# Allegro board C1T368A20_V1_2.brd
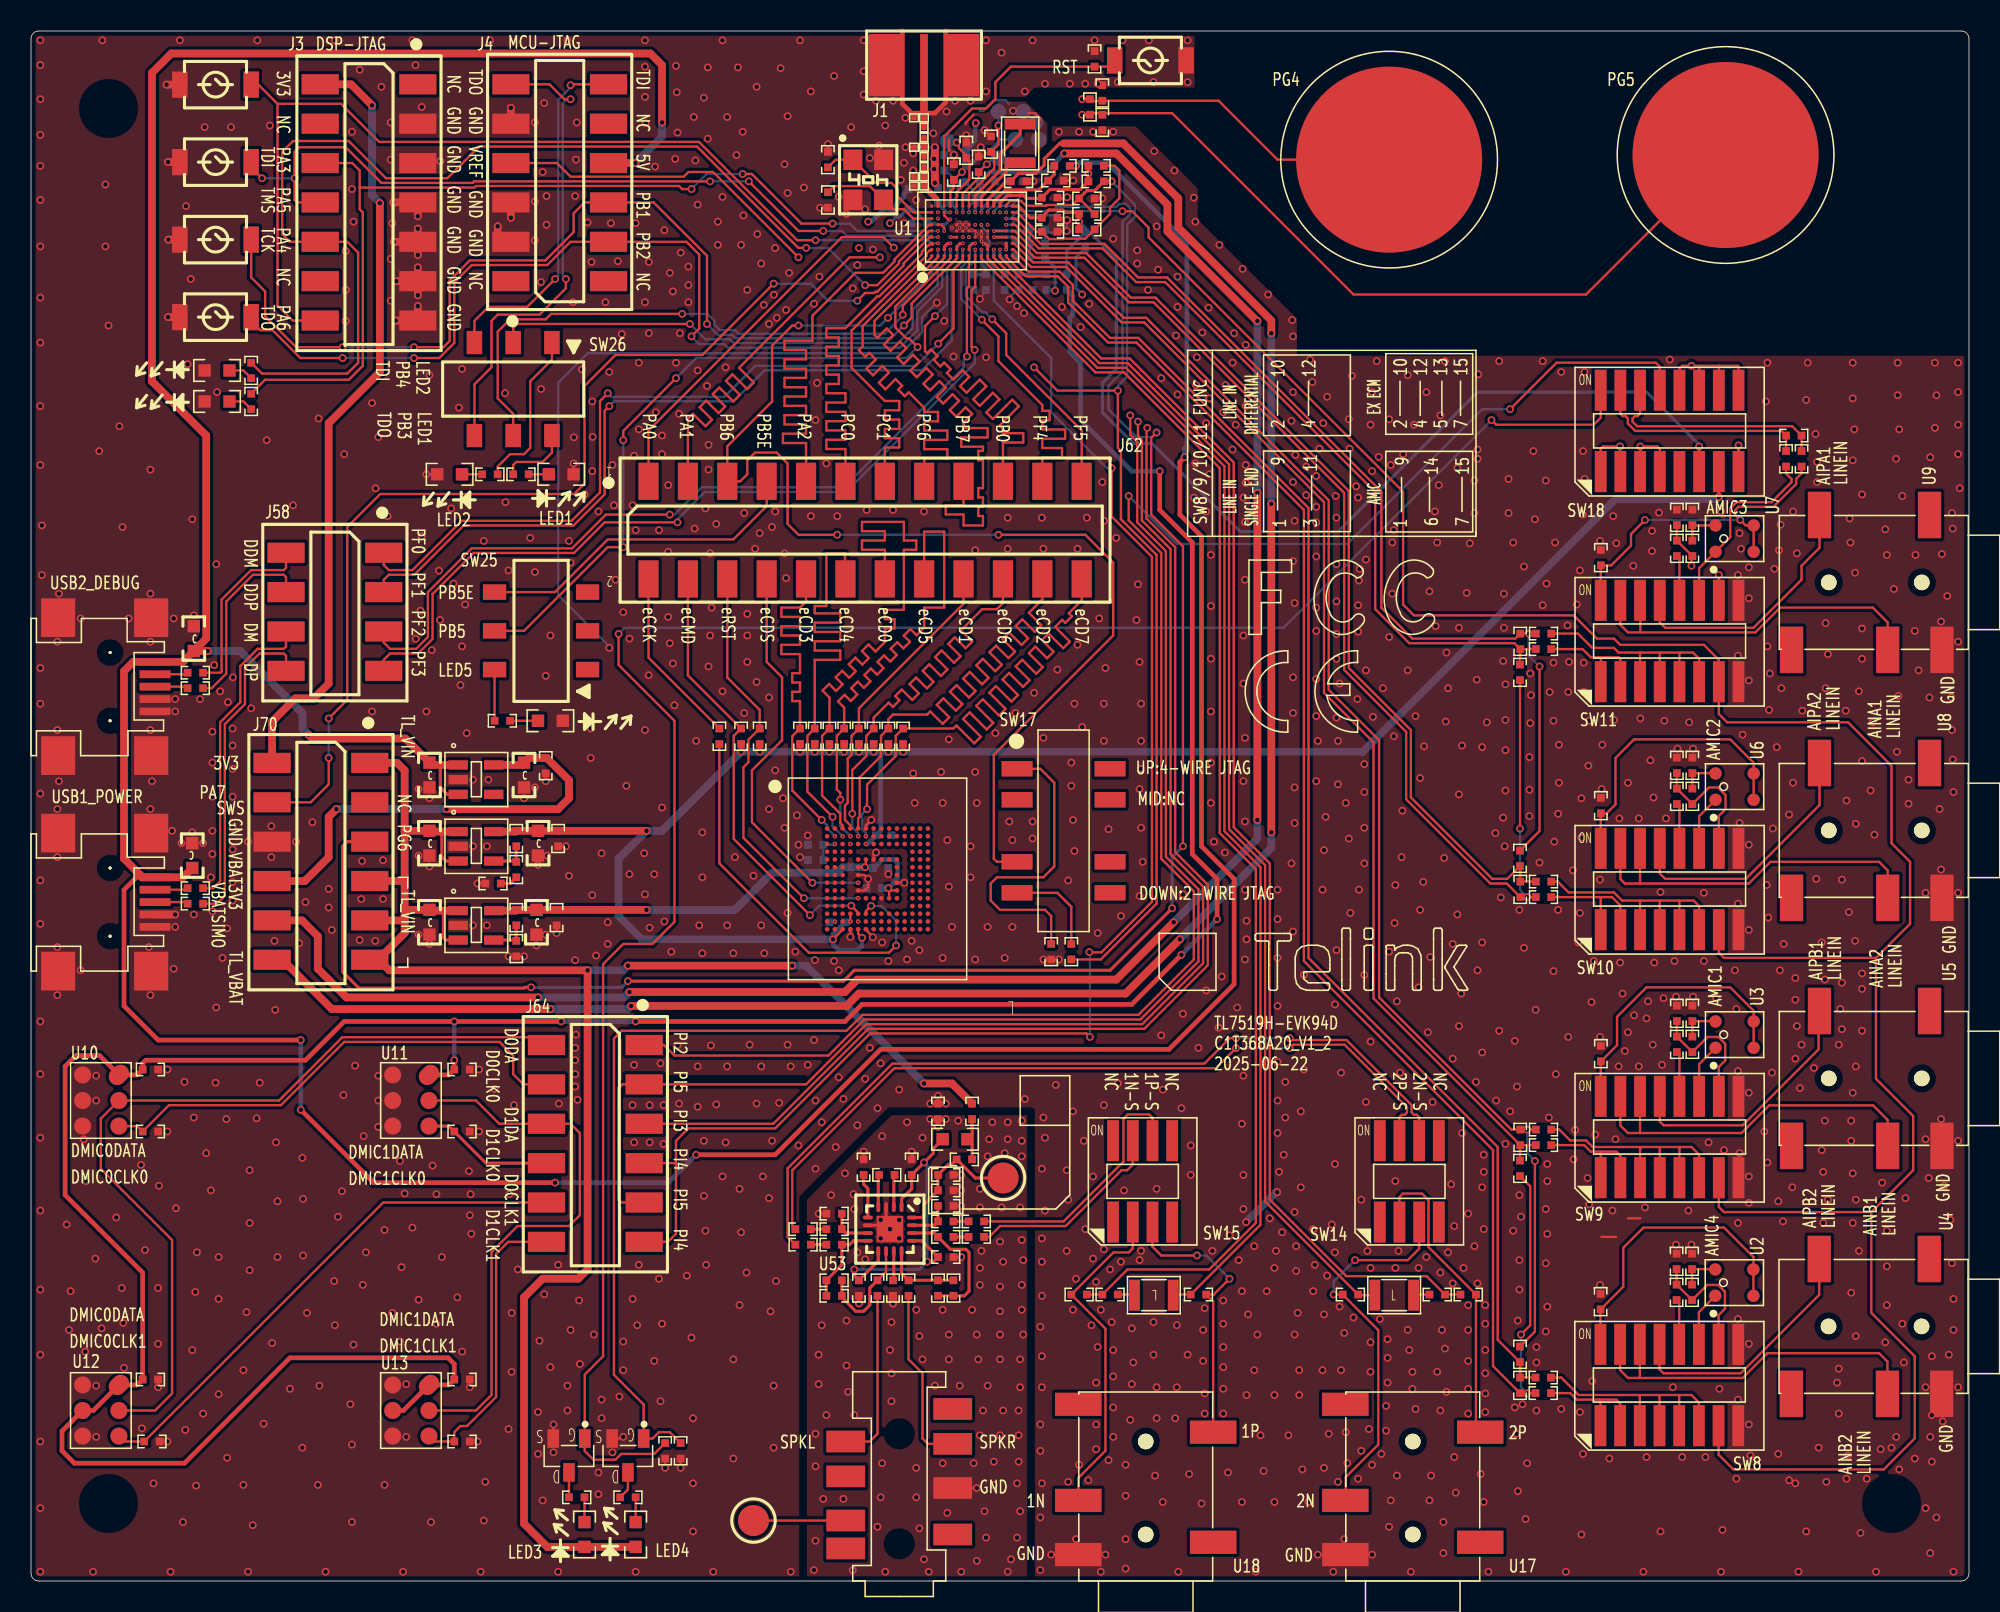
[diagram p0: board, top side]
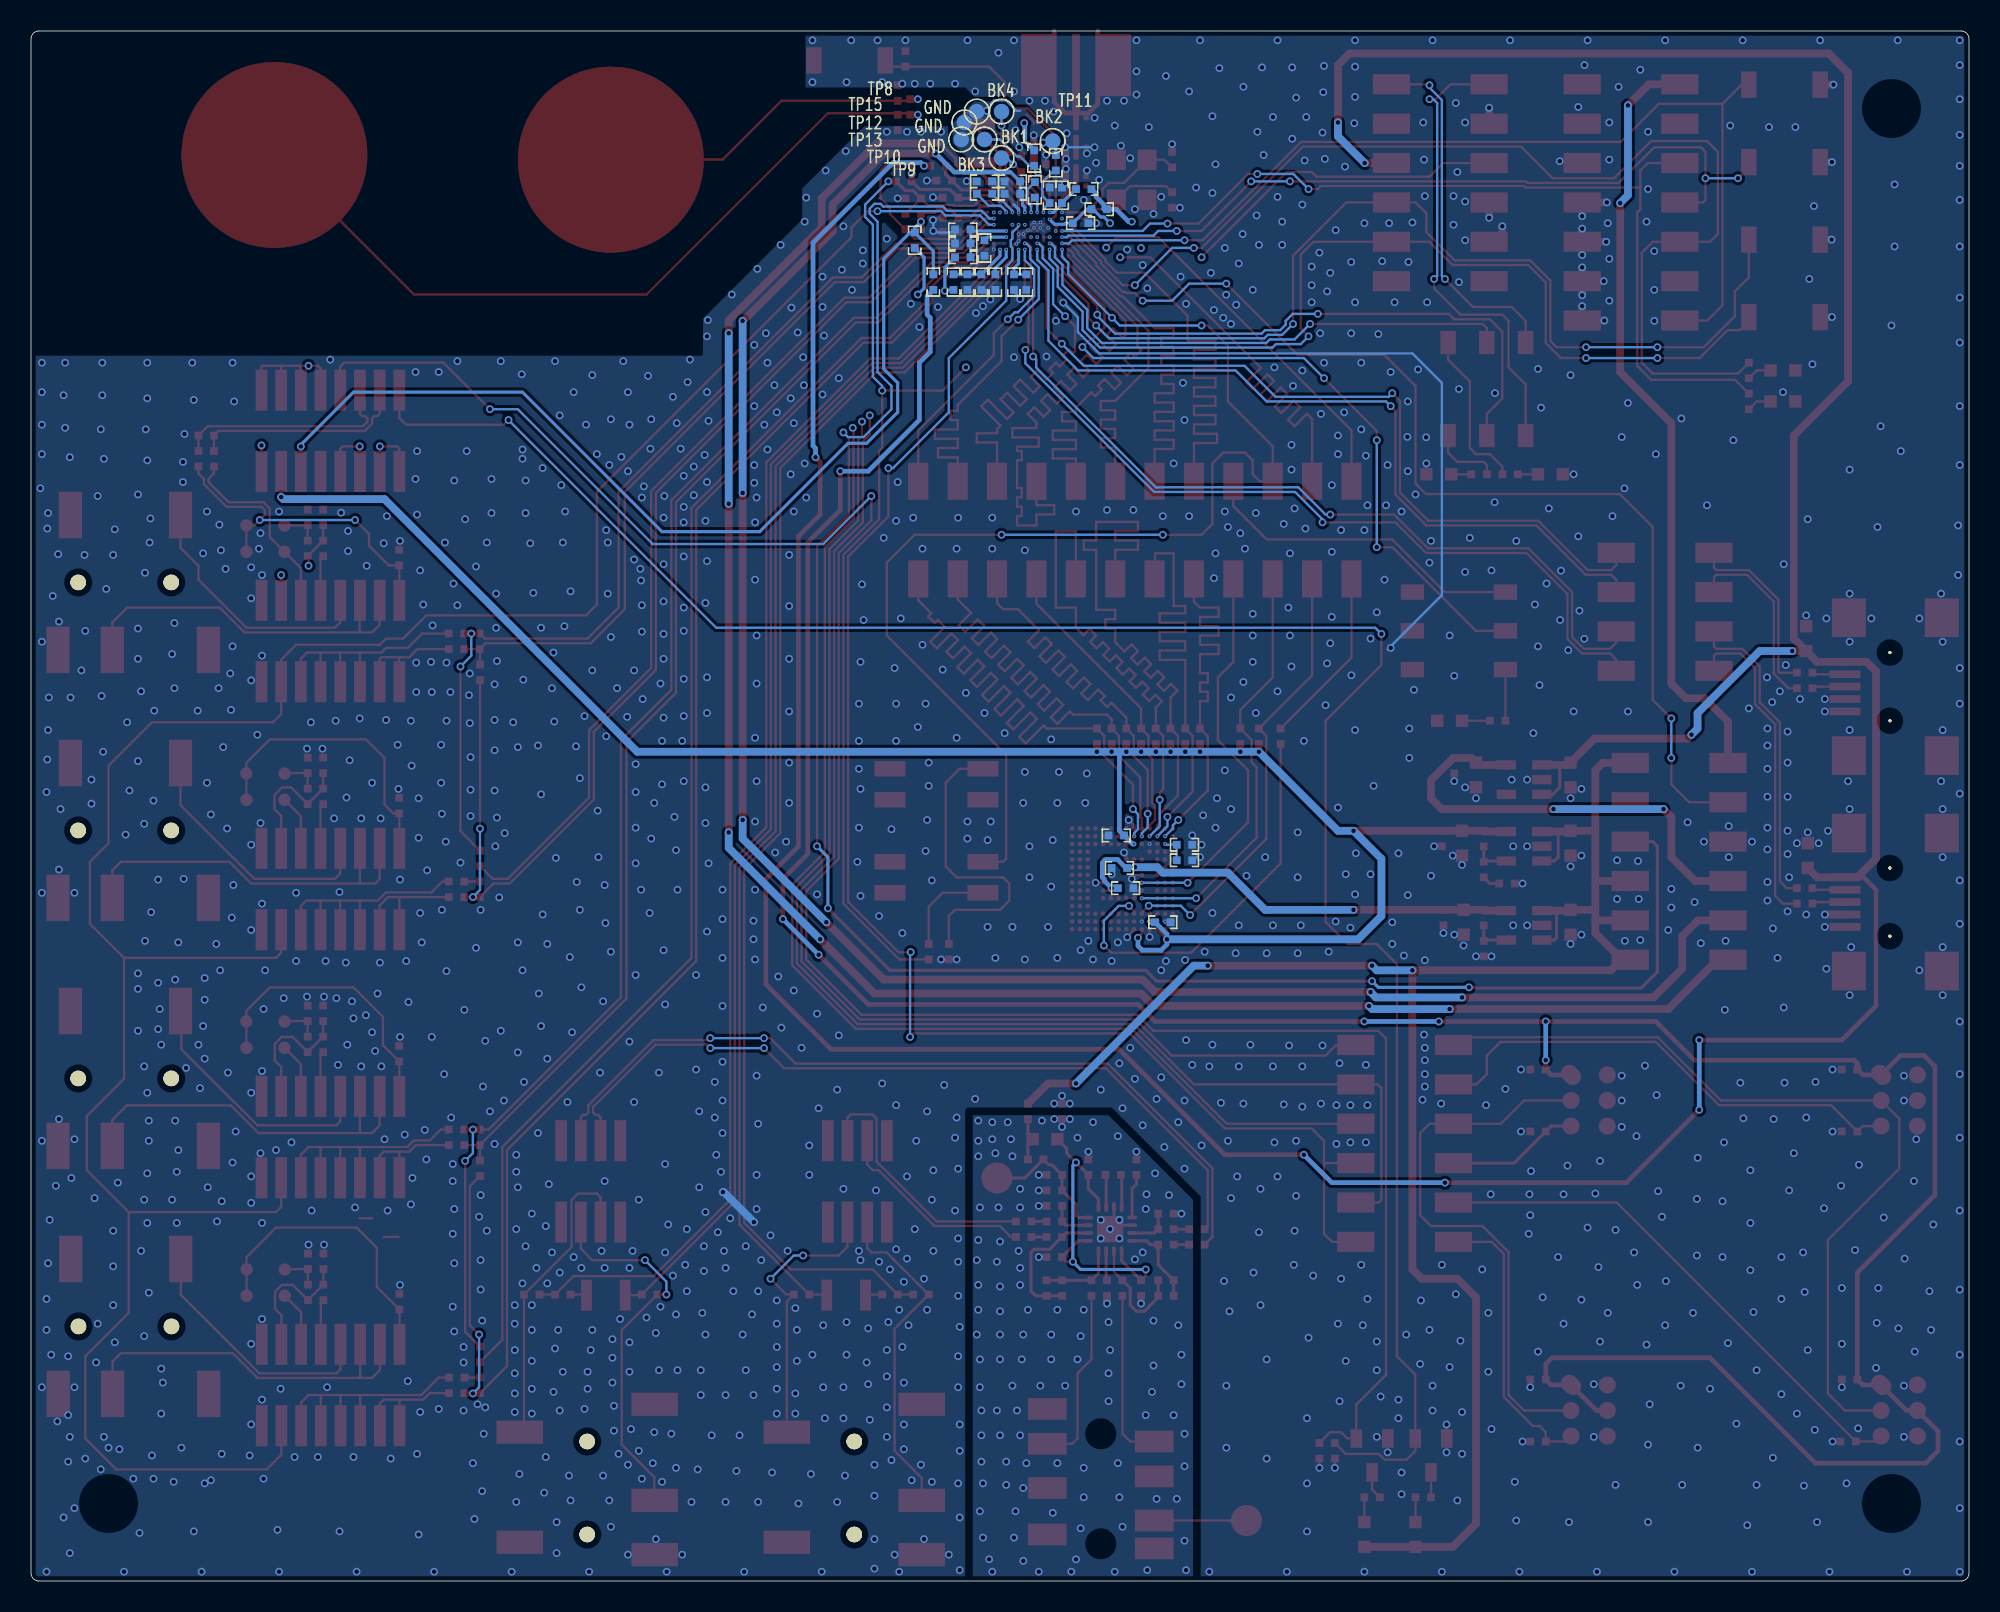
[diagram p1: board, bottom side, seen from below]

Outline 125 x 100 mm; copper layers: TOP, GND, POWER, BOTTOM. Coordinates in mm from the lower left corner of the outline.
Outline path: 0,99.5 arc(0.15,99.85) 0.5,100 124.5,100 arc(124.85,99.85) 125,99.5 125,0.5 arc(124.85,0.15) 124.5,0 0.5,0 arc(0.15,0.15) 0,0.5 0,99.5

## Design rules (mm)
constraint set DEFAULT: min track width 0.15
net group TL_EMMCCMD: nets TL_EMMCCMD TL_PA1
net group TL_EMMCD0: nets TL_EMMCD0 TL_PC1
net group TL_EMMCD1: nets TL_EMMCD1 TL_PB7
net group TL_EMMCD2: nets TL_EMMCD2 TL_PF4
net group TL_EMMCD3: nets TL_EMMCD3 TL_PA2
net group TL_EMMCD4: nets TL_EMMCD4 TL_PC0
net group TL_EMMCD5: nets TL_EMMCD5 TL_PC6
net group TL_EMMCD6: nets TL_EMMCD6 TL_PB0
net group TL_EMMCD7: nets TL_EMMCD7 TL_PF5
net group TL_EMMCDS: nets TL_EMMCDS TL_PB5_EMMC
net group TL_EMMCRSTN: nets TL_EMMCRSTN TL_PB6
net group TL_EMMCCK: nets N20915988 TL_EMMCCK TL_PA0

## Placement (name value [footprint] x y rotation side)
C2  1.8pF  [0201]  57.27 92.5 0 top
C3  NC  [0201]  57.27 94.4 0 top
C4  1uF  [0402]  68.1 89.2 0 top
C5  1uF  [0402]  59.3 89.4 90 bottom
C6  1uF  [0402]  58.5 89.4 90 bottom
C8  1uF  [0402]  68.6 98.2 90 top
C10  1uF  [0402]  57.3 87.6 180 bottom
C11  10uF  [0402]  66.1 90.35 0 top
C12  10uF  [0402]  63.7 90.31 0 top
C13  4.7uF  [0402]  62.8 83.8 270 bottom
C15  10uF  [0603C]  25.7 42.5 270 top
C16  10uF  [0402]  60.8 83.8 270 bottom
C17  0.1uF  [0402]  61.6 83.8 270 bottom
C19  10uF  [0603C]  25.7 47.6 270 top
C20  10uF  [0402]  65.7 89.25 0 top
C21  0.1uF  [0402]  34 47.9 270 top
C23  10uF  [0402]  65.7 87.95 0 top
C24  4.7uF  [0402]  63.5 86 270 bottom
C25  10uF  [0402]  64.6 83.8 270 bottom
C26  0.1uF  [0402]  63.7 83.8 270 bottom
C27  1uF  [0402]  65.7 87.05 0 top
C28  10uF  [0402]  61.7 90.3 0 bottom
C29  4.7uF  [0402]  61.92 92.7 90 top
C30  4.7uF  [0402]  61.12 91.4 90 top
C31  4.7uF  [0402]  60.33 92.3 90 top
C32  4.7uF  [0402]  59.52 90.9 90 top
C33  10uF  [0402]  64.9 86.3 0 bottom
C34  0.1uF  [0402]  64.9 87.2 0 bottom
C35  NC  [0402]  51.4 89.1 90 top
C36  NC  [0402]  51.4 91.7 270 top
C39  1uF  [0402]  107.14 20.62 90 top
C40  1uF  [0402]  107.16 36.62 90 top
C41  1uF  [0402]  106.14 20.62 90 top
C42  1uF  [0402]  106.16 36.62 90 top
C43  270nF  [0402]  97.54 13.12 0 top
C44  270nF  [0402]  97.56 29.12 0 top
C45  270nF  [0402]  97.54 12.12 0 top
C46  270nF  [0402]  97.56 28.12 0 top
C47  1uF  [0402]  107.16 68.62 90 top
C48  1uF  [0402]  107.16 52.62 90 top
C49  1uF  [0402]  106.16 52.62 90 top
C50  1uF  [0402]  106.16 68.62 90 top
C51  270nF  [0402]  97.56 61.12 0 top
C52  270nF  [0402]  97.56 45.12 0 top
C53  270nF  [0402]  97.56 60.12 0 top
C54  270nF  [0402]  97.56 44.12 0 top
C59  0.1uF  [0402]  7.7 33 0 top
C60  0.1uF  [0402]  27.8 13 0 top
C61  0.1uF  [0402]  7.7 13 0 top
C62  0.1uF  [0402]  27.8 33 0 top
C69  1uF  [0402]  53.7 26.7 90 top
C70  1uF  [0402]  55.2 26.2 180 top
C71  0.1uF  [0402]  55.6 18.9 270 top
C72  15pF  [0402]  58.5 18.9 90 top
C73  1uF  [0402]  59 20.9 0 top
C78  0R  [0402]  92.7 18.48 0 top
C79  0R  [0402]  67.6 18.48 180 top
C80  0R  [0402]  85.1 18.48 180 top
C81  0R  [0402]  75.3 18.48 0 top
C82  10uF  [0603C]  10.4 46.8 90 top
C91  10uF  [0603C]  25.7 52 270 top
C92  10uF  [0603C]  31.8 52 270 top
C93  0.1uF  [0402]  33.2 52.6 270 top
C112  1.5pF  [0201]  57.27 90.6 0 top
C113  0.1uF  [0402]  61.7 89.5 0 bottom
C427  2.2uF  [0402]  52 42.5 180 bottom
C428  2.2uF  [0402]  55 48.1 0 bottom
C429  4.7uF  [0402]  54.8 46 0 bottom
C430  4.7uF  [0402]  54.4 44.7 180 bottom
C431  0.1uF  [0402]  50.6 47.5 180 bottom
C432  0.1uF  [0402]  50.6 46.5 180 bottom
C433  10uF  [0603C]  10.5 60.8 270 top
C460  1uF  [0402]  53.4 18.9 270 top
C461  1uF  [0402]  56.8 26.7 90 top
C462  4.7uF  [0402]  60.97 22.2 180 top
C463  4.7uF  [0402]  60.97 23.2 180 top
C464  4.7uF  [0402]  49.8 22.7 0 top
C465  4.7uF  [0402]  49.8 21.7 0 top
C466  0.1uF  [0402]  59 26.2 0 top
C467  15pF  [0402]  51.8 18.4 0 top
C468  10uF  [0603C]  32.6 42.5 270 top
C469  0.1uF  [0402]  33.9 42.8 270 top
C470  10uF  [0603C]  32.7 47.6 270 top
C471  510pF  [0402]  63.5 89.5 180 bottom
C472  510pF  [0402]  60.25 89.75 270 bottom
C473  NC  [0402]  68.3 95.1 270 top
C474  5.1pF  [0402]  69.1 94.1 270 top
C475  5.1pF  [0402]  69.1 96 270 top
C476  270nF  [0402]  113.2 72.4 270 top
C477  270nF  [0402]  114.2 72.4 270 top
D1  Blue  [0603-LED]  35.7 3 90 top
D5  ULC0322P10LV  [0201]  57.27 90 180 top
D6  Yellow  [0603-LED]  33.5 55.5 0 top
D8  Red  [0603-LED]  27 71.4 180 top
D9  White  [0603-LED]  34.2 71.4 0 top
D10  Green  [0603-LED]  39 3 90 top
D11  Green  [0603-LED]  12 78.1 180 top
D12  Blue  [0603-LED]  12 76.1 180 top
J1  RFIN  [SMA-H]  57.6 97.8 270 top
J3  DSP_JTAG  [SMD254M-2X7_RX1_30Y2_40]  21.8 88.94 90 top
J4  D25_JTAG  [SMD254M-2X6_RX1_30Y2_40]  34.1 90.21 270 top
J21  USB_MiniABF  [USB-MINI-F5]  8 43.8 270 top
J22  USB_MiniABF  [USB-MINI-F5]  8 57.7 270 top
J57  M+L/R  [PJ-382-8P]  56 -1 90 top
J58  USB  [SMD254M-2X4_RX1_30Y2_40]  19.6 62.53 90 top
J62  EMMC  [SMD254M-2X12_RX1_30Y2_40]  53.8 67.8 180 top
J64  DMIC2  [SMD254M-2X6_RX1_30Y2_40]  36.4 28.23 90 top
J70  SWSPWR  [SMD254M-2X6_RX1_30Y2_40]  18.7 46.43 90 top
L1  3nH  [0201]  57.6 91.55 90 top
L2  1.5nH  [0201]  57.6 93.45 90 top
L3  EFE201612E-1R0M  [1008L]  63.8 92.75 270 top
L5  NC  [1008L]  87.92 18.44 0 top
L6  NC  [1008L]  72.42 18.44 180 top
L11  BEAD-600R  [0603L]  59.6 28.5 180 top
Q2  SI2302  [MOS_SOT-23]  34.7 8.1 180 top
Q3  SI2302  [MOS_SOT-23]  38.5 8.1 180 top
R5  1K  [0402]  35.2 5.4 180 top
R8  2.2K  [0402]  107.16 34.62 90 top
R9  2.2K  [0402]  106.14 18.62 90 top
R10  2.2K  [0402]  107.14 18.62 90 top
R11  2.2K  [0402]  106.16 34.62 90 top
R12  0R  [0402]  101.26 34.02 90 top
R13  0R  [0402]  101.24 18.02 90 top
R14  NC  [0402]  96.04 12.62 270 top
R15  NC  [0402]  96.06 28.62 270 top
R16  2.2K  [0402]  107.16 50.62 90 top
R17  2.2K  [0402]  106.16 66.62 90 top
R18  2.2K  [0402]  106.16 50.62 90 top
R19  2.2K  [0402]  107.16 66.62 90 top
R20  0R  [0402]  101.26 50.02 90 top
R21  0R  [0402]  101.26 66.02 90 top
R22  NC  [0402]  96.06 44.62 270 top
R23  NC  [0402]  96.06 60.62 270 top
R24  100K  [0402]  7.7 29 180 top
R25  100K  [0402]  27.8 29 180 top
R26  100K  [0402]  7.8 9 180 top
R27  100K  [0402]  27.8 9 180 top
R30  20K / 1%  [0402]  59 23.2 180 top
R31  20K / 1%  [0402]  59 24.2 180 top
R35  1K  [0402]  65.8 40.6 90 top
R36  1K  [0402]  67.1 40.6 90 top
R38  0R  [0402]  56.6 18.9 270 top
R39  20K / 1%  [0402]  59.5 18.9 90 top
R43  NC  [0402]  90.7 18.48 180 top
R44  NC  [0402]  69.6 18.48 0 top
R45  NC/2R  [0402]  66.5 91.3 180 top
R47  33  [0402R]  10.6 44.7 0 top
R48  33  [0402R]  10.6 43.7 0 top
R50  100K  [0402]  60.2 27.2 180 top
R53  33  [0402R]  10.6 58.6 0 top
R55  33  [0402R]  10.6 57.6 0 top
R73  NC  [0402]  96.04 14.62 90 top
R74  NC  [0402]  96.04 26.62 90 top
R75  NC  [0402]  96.04 46.62 90 top
R76  NC  [0402]  96.04 58.62 90 top
R78  0R  [0402]  63.5 90.3 0 bottom
R599  10K  [0402]  45.8 54.5 90 top
R601  10K  [0402]  51.5 54.5 90 top
R602  10K  [0402]  53.4 54.5 90 top
R603  10K  [0402]  55.3 54.5 90 top
R604  10K  [0402]  49.6 54.5 90 top
R605  10K  [0402]  50.55 54.5 90 top
R606  10K  [0402]  52.45 54.5 90 top
R607  10K  [0402]  54.35 54.5 90 top
R608  10K  [0402]  56.25 54.5 90 top
R661  10K  [0402]  47 54.5 90 top
R666  27R  [0402]  44.4 54.5 270 top
R668  20K / 1%  [0402]  59 22.2 180 top
R687  20K / 1%  [0402]  51.8 23.7 0 top
R688  20K / 1%  [0402]  51.8 22.7 0 top
R689  20K / 1%  [0402]  51.8 21.7 0 top
R690  0R  [0402]  54.6 18.9 270 top
R692  20K / 1%  [0402]  51.8 19.4 0 top
R711  0R  [0402]  58.5 30.3 270 top
R712  1M  [0402]  59 25.2 0 top
R713  0R  [0402]  60.7 30.3 270 top
R715  45.3K-1%  [0402]  31.3 42.8 270 top
R717  10K-1%  [0402]  31.3 40.8 270 top
R718  NC  [0402]  113.7 73.9 0 top
R721  45.3K-1%  [0402]  31.3 47.9 270 top
R723  12.4K-1%  [0402]  31.3 45.9 270 top
R724  9.1K-1%  [0402]  29.8 45 180 top
R725  1K  [0402]  30.4 55.5 0 top
R727  1K  [0402]  29.6 71.4 180 top
R728  1K  [0402]  31.6 71.4 0 top
R729  1K  [0402]  38.5 5.4 180 top
R730  0R/NC  [0402]  68.7 90.3 0 top
R731  NC/0R  [0402]  68.1 88.2 0 top
R732  0R/NC  [0402]  68.7 91.3 0 top
R733  NC/0R  [0402]  68.1 87.2 0 top
R734  0R/NC  [0402]  66.8 83.8 270 bottom
R735  0R/NC  [0402]  58.9 91.5 270 bottom
R736  NC/0R  [0402]  56.1 88.5 180 bottom
R737  0R/NC  [0402]  57.1 89.8 180 bottom
R738  0R/NC  [0402]  64.9 85.4 0 bottom
R739  0R/NC  [0402]  65.5 83.8 270 bottom
R740  0R/NC  [0402]  60.3 91.8 90 bottom
R741  0R/NC  [0402]  68 86.5 270 bottom
R742  10K  [0402]  41.9 8.4 270 top
R743  10K  [0402]  40.9 8.4 270 top
R744  1K  [0402]  14.2 78.1 270 top
R745  1K  [0402]  14.2 76.1 270 top
SP5  SolderPad200  [TP200]  62.7 26 0 top
SP6  SolderPad200  [TP200]  46.6 3.9 90 top
SW1  But1  [BUTSMD2PX4_00Y3_00_NH]  72.2 98.1 90 top
SW8  DU-08P  [EHS-JH_1P27_8X2]  105.67 12.64 0 top
SW9  DU-08P  [EHS-JH_1P27_8X2]  105.69 28.64 0 top
SW10  DU-08P  [EHS-JH_1P27_8X2]  105.69 44.64 0 top
SW11  DU-08P  [EHS-JH_1P27_8X2]  105.69 60.64 0 top
SW14  DU-04P  [EHS-JH_1P27_4X2]  88.9 25.78 0 top
SW15  DU-04P  [EHS-JH_1P27_4X2]  71.7 25.78 0 top
SW17  MINI_SLIDE_SWITCH  [SW-SMD-8PIN-12P95X3P5-2]  66.6 48.4 270 top
SW18  DU-08P  [EHS-JH_1P27_8X2]  105.69 74.2 0 top
SW20  BUT  [BUTSMD2PX4_00Y3_00_NH]  11.9 86.54 270 top
SW21  BUT  [BUTSMD2PX4_00Y3_00_NH]  11.9 81.54 270 top
SW23  BUT  [BUTSMD2PX4_00Y3_00_NH]  11.9 91.54 270 top
SW24  BUT  [BUTSMD2PX4_00Y3_00_NH]  11.9 96.54 270 top
SW25  LED+EMMC  [SW-SMD-6PIN-9P1X3P5-2P5]  32.9 61.3 270 top
SW26  LED+JTAG  [SW-SMD-6PIN-9P1X3P5-2P5]  31.1 76.9 0 top
TP5  CTB PAD4  [TP12MM]  87.6 91.7 0 top
TP7  CTB PAD  [TP12MM]  109.3 92 0 top
TP8  BK4  [TP100]  62.4 94.8 180 bottom
TP9  BK3  [TP100]  62.4 91.8 180 bottom
TP10  BK1  [TP100]  63.5 93 180 bottom
TP11  BK2  [TP100]  59.1 92.9 180 bottom
TP12  GND  [TP100]  64.8 94.1 180 bottom
TP13  GND  [TP100]  65 93 180 bottom
TP15  GND  [TP100]  64 94.8 180 bottom
U1  TL7519H  [BGA_4X6_94PIN_0P4]  60.7 87.1 90 top
U2  WMM7037AT2  [GA_BFA423_A83]  109.86 19.25 90 top
U3  WMM7037AT2  [GA_BFA423_A83]  109.88 35.25 90 top
U4  PJ327  [PJ-327]  124.94 16.42 270 top
U5  PJ327  [PJ-327]  124.96 32.42 270 top
U6  WMM7037AT2  [GA_BFA423_A83]  109.88 51.25 90 top
U7  WMM7037AT2  [GA_BFA423_A83]  109.88 67.25 90 top
U8  PJ327  [PJ-327]  124.96 48.42 270 top
U9  PJ327  [PJ-327]  124.96 64.42 270 top
U10  WMM7047DTFN0  [DMIC_SPM0423HM4H-WB]  4.5 31 270 top
U11  WMM7047DTFN0  [DMIC_SPM0423HM4H-WB]  24.5 31 270 top
U12  WMM7047DTFN0  [DMIC_SPM0423HM4H-WB]  4.5 11 270 top
U13  WMM7047DTFN0  [DMIC_SPM0423HM4H-WB]  24.5 11 270 top
U17  PJ327  [PJ-327]  89.12 0 180 top
U18  PJ327  [PJ-327]  71.9 0 180 top
U21  CE1132-3.3V  [SOT-23-5]  28.7 51.7 270 top
U53  MAX97220AETE+  [QFN_3X3_16PIN_0P5_1P70X1P70]  55.4 22.7 270 top
U54  CE6300-ADJ  [SOT-23-5]  28.7 42.3 270 top
U55  CE6300-ADJ  [SOT-23-5]  28.7 47.4 270 top
U56  MKEV008GCB-SC510  [FBGA153]  54.6 45.3 0 top
Y2  48MHz-6pF-+/-10ppm  [OSCCC250X320X110]  54 90.4 0 top

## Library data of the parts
C2 C3 C112 = C1608_NC: Tolerance: RichardLC; User Part Number: pn
C4-C6 C8 C10-C13 C16 C17 C20 C21 C23-C34 C39-C54 C59-C62 C69-C73 C93 C113 C427-C432 C460-C467 C469 C471-C477 = C1005X5R1C104K
C15 C19 C82 C91 C92 C433 C468 C470 = C1608X5R0J106M
C35 C36 = C1005_NC
C78-C81 = C1005X5R1C105K
D1 D6 D8-D12 = 0603D_Green
D5 = ESD5B5_0.0ST1G: Tolerance: RichardLC; User Part Number: pn
J1 = SMA_JACK_2
J3 = CON_0.54mm_2x7: Tolerance: RichardLC
J4 J64 J70 = HEADER 6X2: Tolerance: RichardLC
J21 J22 = USB_MiniABF_5pin: Tolerance: RichardLC; User Part Number: pn
J57 = PJ327_2
J58 = HEADER 4X2: Tolerance: RichardLC
J62 = HEADER 12X2: Tolerance: RichardLC; signal model: HEADER_12X2_SMD254M-2X12_RX1_30Y2_40_EMMC_EMMC
L1 L2 L5 L6 = MLK1608_000R: Tolerance: RichardLC; User Part Number: pn
L3 = IND: Tolerance: RichardLC; User Part Number: pn
L11 = IND
Q2 Q3 = NMOS_SI2302
R5 R715 R717 R721 R723-R725 R727-R729 R744 R745 = RS0402K102JT
R8-R27 R30 R31 R38 R39 R43-R45 R50 R73-R76 R668 R687-R690 R692 R711-R713 R718 R730-R741 = RS0402K104JT
R35 R36 R742 R743 = RS0402K103JT
R47 R48 R53 R55 = RS0603K330JT
R78 = RS0603K102JT
R599 R601-R608 R661 = RS0402K330JT
R666 = RS0402K330JT: signal model: RS0402K330JT_0402_27R_27R
SP5 SP6 = SolderPad200: User Part Number: pn; Tolerance: RichardLC
SW1 SW20 SW21 SW23 SW24 = SW2PIN_3x4
SW8-SW11 SW18 = EHS-JH-108: Tolerance: RichardLC
SW14 SW15 = EHS-JH-104: Tolerance: RichardLC
SW17 = MINI_SLIDE_SWITCH
SW25 SW26 = SW_SL_DPDT: User Part Number: pn; Tolerance: RichardLC
TP5 TP7 = TEST POINT
TP8-TP13 TP15 = TestPad100
U1 = TL7519H-BGA94
U2 U3 U6 U7 = MULPS4CX-RM5_0
U4 U5 U8 U9 U17 U18 = PJ327
U10-U13 = LD1117/SO_0
U21 = XC6219_5.3V_SOT-23-5
U53 = TLSR8368EP16_1
U54 U55 = XC6219_1.3V_SOT-23-5
U56 = H26M88002AMR
Y2 = CRYSTAL4/SM_0

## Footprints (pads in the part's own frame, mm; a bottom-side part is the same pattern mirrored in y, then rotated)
0201
  rect 0.35x0.33 smd: 1(-0.325,0) 2(0.325,0)
0402
  rect 0.5x0.5 smd: 1(-0.5,0) 2(0.5,0)
0402R
  rect 0.5x0.5 smd: 1(-0.5,0) 2(0.5,0)
0603-LED
  rect 0.8x0.8 smd: A(-0.8,0) C(0.8,0)
0603C
  rect 0.8x0.8 smd: 1(-0.8,0) 2(0.8,0)
0603L
  rect 0.8x0.8 smd: 1(-0.8,0) 2(0.8,0)
1008L
  rect 0.7x2 smd: 1(-1.25,0) 2(1.25,0)
BGA_4X6_94PIN_0P4
  round 0.22 smd: A1(-1.6,2.6) A2(-1.2,2.6) A3(-0.8,2.6) A4(-0.4,2.6) A5(0,2.6) A6(0.4,2.6) A7(0.8,2.6) A8(1.2,2.6) A9(1.6,2.6) B1(-1.6,2.2) B2(-1.2,2.2) B3(-0.8,2.2) B4(-0.4,2.2) B5(0,2.2) B6(0.4,2.2) B7(0.8,2.2) B8(1.2,2.2) B9(1.6,2.2) C1(-1.6,1.8) C2(-1.2,1.8) C8(1.2,1.8) C9(1.6,1.8) D1(-1.6,1.4) D2(-1.2,1.4) D8(1.2,1.4) D9(1.6,1.4) E1(-1.6,1) E2(-1.2,1) E4(-0.4,1) E5(0,1) E6(0.4,1) E8(1.2,1) E9(1.6,1) F1(-1.6,0.6) F2(-1.2,0.6) F4(-0.4,0.6) F5(0,0.6) F6(0.4,0.6) F8(1.2,0.6) F9(1.6,0.6) G1(-1.6,0.2) G2(-1.2,0.2) G4(-0.4,0.2) G5(0,0.2) G6(0.4,0.2) G8(1.2,0.2) G9(1.6,0.2) H1(-1.6,-0.2) H2(-1.2,-0.2) H4(-0.4,-0.2) H5(0,-0.2) H6(0.4,-0.2) H8(1.2,-0.2) H9(1.6,-0.2) J1(-1.6,-0.6) J2(-1.2,-0.6) J4(-0.4,-0.6) J5(0,-0.6) J6(0.4,-0.6) J8(1.2,-0.6) J9(1.6,-0.6) K1(-1.6,-1) K2(-1.2,-1) K4(-0.4,-1) K5(0,-1) K6(0.4,-1) K8(1.2,-1) K9(1.6,-1) L1(-1.6,-1.4) L2(-1.2,-1.4) L8(1.2,-1.4) L9(1.6,-1.4) M1(-1.6,-1.8) M2(-1.2,-1.8) M8(1.2,-1.8) M9(1.6,-1.8) N1(-1.6,-2.2) N2(-1.2,-2.2) N3(-0.8,-2.2) N4(-0.4,-2.2) N5(0,-2.2) N6(0.4,-2.2) N7(0.8,-2.2) N8(1.2,-2.2) N9(1.6,-2.2) P1(-1.6,-2.6) P2(-1.2,-2.6) P3(-0.8,-2.6) P4(-0.4,-2.6) P5(0,-2.6) P6(0.4,-2.6) P7(0.8,-2.6) P8(1.2,-2.6) P9(1.6,-2.6)
BUTSMD2PX4_00Y3_00_NH
  rect 1.7x1 smd: 1(0,2.3) 2(0,-2.3)
DMIC_SPM0423HM4H-WB
  round 1.1 smd: 1(-1.65,-1.17) 2(0,-1.17) 3(1.65,-1.17) 4(1.65,1.17) 5(0,1.17)
  oval 1.4x1.1 smd rot 135: 6(-1.65,1.17)
EHS-JH_1P27_4X2
  rect 0.76x2.65 smd: 1(-1.905,-2.625) 2(-0.635,-2.625) 3(0.635,-2.625) 4(1.905,-2.625) 5(-1.905,2.625) 6(-0.635,2.625) 7(0.635,2.625) 8(1.905,2.625)
EHS-JH_1P27_8X2
  rect 0.76x2.65 smd: 1(-4.445,-2.625) 2(-3.175,-2.625) 3(-1.905,-2.625) 4(-0.635,-2.625) 5(0.635,-2.625) 6(1.905,-2.625) 7(3.175,-2.625) 8(4.445,-2.625) 9(-4.445,2.625) 10(-3.175,2.625) 11(-1.905,2.625) 12(-0.635,2.625) 13(0.635,2.625) 14(1.905,2.625) 15(3.175,2.625) 16(4.445,2.625)
FBGA153
  round 0.3 smd: A1(-3.25,3.25) A2(-2.75,3.25) A3(-2.25,3.25) A4(-1.75,3.25) A5(-1.25,3.25) A6(-0.75,3.25) A7(-0.25,3.25) A8(0.25,3.25) A9(0.75,3.25) A10(1.25,3.25) A11(1.75,3.25) A12(2.25,3.25) A13(2.75,3.25) A14(3.25,3.25) B1(-3.25,2.75) B2(-2.75,2.75) B3(-2.25,2.75) B4(-1.75,2.75) B5(-1.25,2.75) B6(-0.75,2.75) B7(-0.25,2.75) B8(0.25,2.75) B9(0.75,2.75) B10(1.25,2.75) B11(1.75,2.75) B12(2.25,2.75) B13(2.75,2.75) B14(3.25,2.75) C1(-3.25,2.25) C2(-2.75,2.25) C3(-2.25,2.25) C4(-1.75,2.25) C5(-1.25,2.25) C6(-0.75,2.25) C7(-0.25,2.25) C8(0.25,2.25) C9(0.75,2.25) C10(1.25,2.25) C11(1.75,2.25) C12(2.25,2.25) C13(2.75,2.25) C14(3.25,2.25) D1(-3.25,1.75) D2(-2.75,1.75) D3(-2.25,1.75) D4(-1.75,1.75) D12(2.25,1.75) D13(2.75,1.75) D14(3.25,1.75) E1(-3.25,1.25) E2(-2.75,1.25) E3(-2.25,1.25) E5(-1.25,1.25) E6(-0.75,1.25) E7(-0.25,1.25) E8(0.25,1.25) E9(0.75,1.25) E10(1.25,1.25) E12(2.25,1.25) E13(2.75,1.25) E14(3.25,1.25) F1(-3.25,0.75) F2(-2.75,0.75) F3(-2.25,0.75) F5(-1.25,0.75) F10(1.25,0.75) F12(2.25,0.75) F13(2.75,0.75) F14(3.25,0.75) G1(-3.25,0.25) G2(-2.75,0.25) G3(-2.25,0.25) G5(-1.25,0.25) G10(1.25,0.25) G12(2.25,0.25) G13(2.75,0.25) G14(3.25,0.25) H1(-3.25,-0.25) H2(-2.75,-0.25) H3(-2.25,-0.25) H5(-1.25,-0.25) H10(1.25,-0.25) H12(2.25,-0.25) H13(2.75,-0.25) H14(3.25,-0.25) J1(-3.25,-0.75) J2(-2.75,-0.75) J3(-2.25,-0.75) J5(-1.25,-0.75) J10(1.25,-0.75) J12(2.25,-0.75) J13(2.75,-0.75) J14(3.25,-0.75) K1(-3.25,-1.25) K2(-2.75,-1.25) K3(-2.25,-1.25) K5(-1.25,-1.25) K6(-0.75,-1.25) K7(-0.25,-1.25) K8(0.25,-1.25) K9(0.75,-1.25) K10(1.25,-1.25) K12(2.25,-1.25) K13(2.75,-1.25) K14(3.25,-1.25) L1(-3.25,-1.75) L2(-2.75,-1.75) L3(-2.25,-1.75) L12(2.25,-1.75) L13(2.75,-1.75) L14(3.25,-1.75) M1(-3.25,-2.25) M2(-2.75,-2.25) M3(-2.25,-2.25) M4(-1.75,-2.25) M5(-1.25,-2.25) M6(-0.75,-2.25) M7(-0.25,-2.25) M8(0.25,-2.25) M9(0.75,-2.25) M10(1.25,-2.25) M11(1.75,-2.25) M12(2.25,-2.25) M13(2.75,-2.25) M14(3.25,-2.25) N1(-3.25,-2.75) N2(-2.75,-2.75) N3(-2.25,-2.75) N4(-1.75,-2.75) N5(-1.25,-2.75) N6(-0.75,-2.75) N7(-0.25,-2.75) N8(0.25,-2.75) N9(0.75,-2.75) N10(1.25,-2.75) N11(1.75,-2.75) N12(2.25,-2.75) N13(2.75,-2.75) N14(3.25,-2.75) P1(-3.25,-3.25) P2(-2.75,-3.25) P3(-2.25,-3.25) P4(-1.75,-3.25) P5(-1.25,-3.25) P6(-0.75,-3.25) P7(-0.25,-3.25) P8(0.25,-3.25) P9(0.75,-3.25) P10(1.25,-3.25) P11(1.75,-3.25) P12(2.25,-3.25) P13(2.75,-3.25) P14(3.25,-3.25)
GA_BFA423_A83
  round 0.8 smd: 1(-0.85,1.23) 2(-0.85,-1.23) 3(0.85,-1.23) 4(0.85,1.23)
MOS_SOT-23
  rect 0.75x1.2 smd: 1(-1.016,-1.092) 2(1.016,-1.092) 3(0,1.092)
OSCCC250X320X110
  rect 1.22x1.32 smd: 1(-0.991,1.29) 2(-0.991,-1.29) 3(0.991,-1.29) 4(0.991,1.29)
PJ-327
  round 1 hole 1 unplated: (0,-3) (0,-9)
  rect 3x1.5 smd: 1(-4.35,-2.5) 2(4.35,-5.2) 3(-4.35,-9.6) 4(4.35,-11.4) 5(4.35,-1.7)
PJ-382-8P
  rect 1.4x2.5 smd: 1(4,-3.45) 2(7,-3.45) 3(9.85,-3.45) 4(12.1,-3.45) 5(3.1,3.45) 6(4.9,3.45) 7(7.75,3.45) 8(10,3.45)
QFN_3X3_16PIN_0P5_1P70X1P70
  oval 0.65x0.25 smd: 1(-1.425,0.75) 2(-1.425,0.25) 3(-1.425,-0.25) 4(-1.425,-0.75) 9(1.425,-0.75) 10(1.425,-0.25) 11(1.425,0.25) 12(1.425,0.75)
  oval 0.25x0.65 smd: 5(-0.75,-1.425) 6(-0.25,-1.425) 7(0.25,-1.425) 8(0.75,-1.425) 13(0.75,1.425) 14(0.25,1.425) 15(-0.25,1.425) 16(-0.75,1.425)
  rect 1.7x1.7 smd: 17(0,0)
SMA-H
  rect 5x0.5 smd: 1(0.5,0)
  rect 4x2 smd: 2(0,-2.54) 3(0,2.54) 4(0,-2.54) 5(0,2.54)
SMD254M-2X4_RX1_30Y2_40
  rect 1.3x2.4 smd: 1(3.81,-3.15) 2(3.81,3.15) 3(1.27,-3.15) 4(1.27,3.15) 5(-1.27,-3.15) 6(-1.27,3.15) 7(-3.81,-3.15) 8(-3.81,3.15)
SMD254M-2X6_RX1_30Y2_40
  rect 1.3x2.4 smd: 1(6.35,-3.15) 2(6.35,3.15) 3(3.81,-3.15) 4(3.81,3.15) 5(1.27,-3.15) 6(1.27,3.15) 7(-1.27,-3.15) 8(-1.27,3.15) 9(-3.81,-3.15) 10(-3.81,3.15) 11(-6.35,-3.15) 12(-6.35,3.15)
SMD254M-2X7_RX1_30Y2_40
  rect 1.3x2.4 smd: 1(7.62,-3.15) 2(7.62,3.15) 3(5.08,-3.15) 4(5.08,3.15) 5(2.54,-3.15) 6(2.54,3.15) 7(0,-3.15) 8(0,3.15) 9(-2.54,-3.15) 10(-2.54,3.15) 11(-5.08,-3.15) 12(-5.08,3.15) 13(-7.62,-3.15) 14(-7.62,3.15)
SMD254M-2X12_RX1_30Y2_40
  rect 1.3x2.4 smd: 1(13.97,-3.15) 2(13.97,3.15) 3(11.43,-3.15) 4(11.43,3.15) 5(8.89,-3.15) 6(8.89,3.15) 7(6.35,-3.15) 8(6.35,3.15) 9(3.81,-3.15) 10(3.81,3.15) 11(1.27,-3.15) 12(1.27,3.15) 13(-1.27,-3.15) 14(-1.27,3.15) 15(-3.81,-3.15) 16(-3.81,3.15) 17(-6.35,-3.15) 18(-6.35,3.15) 19(-8.89,-3.15) 20(-8.89,3.15) 21(-11.43,-3.15) 22(-11.43,3.15) 23(-13.97,-3.15) 24(-13.97,3.15)
SOT-23-5
  rect 0.6x1.25 smd: 1(-0.95,-1.145) 2(0,-1.145) 3(0.95,-1.145) 4(0.95,1.145) 5(-0.95,1.145)
SW-SMD-6PIN-9P1X3P5-2P5
  rect 1x1.5 smd: 1(2.5,3) 2(0,3) 3(-2.5,3) 4(-2.5,-3) 5(0,-3) 6(2.5,-3)
SW-SMD-8PIN-12P95X3P5-2
  rect 1x2 smd: 1(-4,-3) 2(-2,-3) 3(2,-3) 4(4,-3) 5(-4,3) 6(-2,3) 7(2,3) 8(4,3)
TP12MM
  round 12 smd: 1(0,0)
TP100
  round 1 smd: 1(0,0)
TP200
  round 2 smd: 1(0,0)
USB-MINI-F5
  round 0.2 hole 0.9 unplated: (-2.2,-2.9) (2.2,-2.9)
  rect 0.5x2 smd: 1(-1.6,0) 2(-0.8,0) 3(0,0) 4(0.8,0) 5(1.6,0)
  rect 2.5x2.2 smd: 6(-4.45,-6.25) 7(4.45,-6.25) 8(-4.45,-0.25) 9(4.45,-0.25)

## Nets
GND: C2.1 C3.1 C4.2 C5.2 C6.2 C8.2 C10.2 C11.2 C12.2 C13.2 C15.2 C16.2 C17.2 C19.2 C20.2 C21.2 C23.2 C24.2 C25.2 C26.2 C27.2 C33.2 C34.2 C35.1 C36.1 C39.2 C40.2 C41.2 C42.2 C47.2 C48.2 C49.2 C50.2 C59.2 C60.2 C61.2 C62.2 C82.2 C91.2 C92.2 C93.2 C112.1 C427.2 C428.2 C429.2 C430.2 C431.2 C432.2 C433.1 C468.2 C469.2 C470.2 C474.2 C475.1 D5.2 D6.C(CATHODE) D8.C(CATHODE) D9.C(CATHODE) D11.C(CATHODE) D12.C(CATHODE) J1.2 J1.3 J1.4 J1.5 J3.3 J3.5 J3.7 J3.9 J3.11 J3.13 J4.3 J4.5 J4.9 J21.4 J21.5 J21.6 J21.7 J21.8 J21.9 J22.4 J22.5 J22.6 J22.7 J22.8 J22.9 J70.6 Q2.2(S) Q3.2(S) R12.2 R13.2 R20.2 R21.2 R24.1 R25.1 R26.1 R27.1 R35.1 R78.2 R711.1 R717.2 R724.2 R742.2 R743.2 SW1.2 SW8.8 SW8.16 SW9.8 SW9.16 SW10.8 SW10.16 SW11.8 SW11.16 SW20.2 SW21.2 SW23.2 SW24.2 U1.A9 U1.B8 U1.E5 U1.E6 U1.F5 U1.F6 U1.G5 U1.G6 U1.H4 U1.H5 U1.J4 U1.J5 U1.K2 U1.K4 U1.K5 U1.N2 U1.N3 U4.5 U5.5 U8.5 U9.5 U10.1 U10.2(SE) U10.3 U11.1 U11.2(SE) U11.3 U12.1 U12.3 U13.1 U13.3 U17.5 U18.5 U21.2(VSS) U54.2(VSS) U55.2(VSS) U56.A6 U56.C4 U56.E7 U56.G5 U56.H10 U56.J5 U56.K8 U56.N2 U56.N5 U56.P4 U56.P6 Y2.2 Y2.4
GND_FIELD SIGNAL: C69.2 C71.2 C73.2 C460.2 C461.2 C466.2 J57.2 R31.1 R687.1 R711.2 R712.2 U53.3 U53.6 U53.17
GND_SIGNAL: C28.2 C29.2 C30.2 C31.2 C32.2 C113.2 R78.1 TP12.1(TP) TP13.1(TP) TP15.1(TP) U1.J8
VBUS: C82.1 C91.1 C433.2 J4.8 J21.1(V_BUS) J22.1(V_BUS) R45.1 U21.1 U21.3
1N: C79.2 SW15.2 U18.2
1P: C81.2 SW15.3 U18.3
2N: C80.2 SW14.3 U17.2
2P: C78.2 SW14.2 U17.3
AINA1: C53.2 SW11.1 SW11.2
AINA1-LINE IN: SW11.10 SW11.11 U9.2
AINA2: C54.2 SW10.1 SW10.2
AINA2-LINE IN: SW10.10 SW10.11 U8.2
AINB1: C46.2 SW9.1 SW9.2
AINB1-LINE IN: SW9.10 SW9.11 U5.2
AINB2: C45.2 SW8.1 SW8.2
AINB2-LINE IN: SW8.10 SW8.11 U4.2
AIPA1: C51.2 SW11.3 SW11.4 SW11.5 SW11.6
AIPA1-LINE IN: SW11.12 U9.3
AIPA2: C52.2 SW10.3 SW10.4 SW10.5 SW10.6
AIPA2-LINE IN: SW10.12 U8.3
AIPB1: C44.2 SW9.3 SW9.4 SW9.5 SW9.6
AIPB1-LINE IN: SW9.12 U5.3
AIPB2: C43.2 SW8.3 SW8.4 SW8.5 SW8.6
AIPB2-LINE IN: SW8.12 U4.3
AMIC-AINA1-1: C477.2 R21.1 SW11.9 U7.2 U7.3
AMIC-AINA2-1: R20.1 SW10.9 U6.2 U6.3
AMIC-AINB1-1: R12.1 SW9.9 U3.2 U3.3
AMIC-AINB2-1: R13.1 SW8.9 U2.2 U2.3
AMIC-BIAS-1: C42.1 R8.1 R11.2 SW9.15
AMIC-BIAS-2: C49.1 R16.1 R18.2 SW10.15
AMIC-BIAS-3: C50.1 R17.2 R19.1 SW11.15 SW18.13 SW18.14 SW18.15 SW18.16
AMIC-BIAS-4: C41.1 R9.2 R10.1 SW8.15
AMIC-OUT-1: SW9.14 U3.1
AMIC-OUT-2: SW10.14 U6.1
AMIC-OUT-3: C476.2 SW11.14 U7.1
AMIC-OUT-4: SW8.14 U2.1
EARPHONE_DECT: J57.6 SP6.1
EXT_3V3: J3.2 J70.2
TL_1V8O: C23.1 R731.1 R733.1 R734.1 R741.1 SW18.6 U1.P9
TL_3V3O: C20.1 R730.1 R732.1 SW18.8 U1.M9
TL_AINA1: C53.1 R23.2 R76.2 U1.P6
TL_AINA2: C54.1 R22.2 R76.1 U1.P4
TL_AINB1: C46.1 R15.2 R74.2 U1.P2
TL_AINB2: C45.1 R14.2 R74.1 U1.N1
TL_AIPA1: C51.1 R23.1 R75.2 U1.P7
TL_AIPA2: C52.1 R22.1 R75.1 U1.P5
TL_AIPB1: C44.1 R15.1 R73.2 U1.P3
TL_AIPB2: C43.1 R14.1 R73.1 U1.P1
TL_ANT1: C112.2 D5.1 L1.1 U1.B9
TL_ANT2: C2.2 L1.2 L2.1
TL_ANT3: C3.2 J1.1 L2.2
TL_AOHP1N_01: C462.1 SW15.6
TL_AOHP1P_01: C463.1 SW15.7
TL_AOHP2N_01: C465.1 SW14.7
TL_AOHP2P_01: C464.1 SW14.6
TL_AOHPA1N: C79.1 R44.1 U1.J1
TL_AOHPA1P: C81.1 L6.1 U1.K1
TL_AOHPA2N: C80.1 L5.1 U1.L1
TL_AOHPA2P: C78.1 R43.1 U1.M1
TL_AVD: C33.1 C34.1 R738.1 U1.N5
TL_BK1_SIMO: C32.1 R740.1 TP10.1(TP) U1.D9
TL_BK2_SIMO: C31.1 R735.1 TP11.1(TP) U1.E9
TL_BK3_SIMO: C30.1 TP9.1(TP) U1.F9
TL_BK4_SIMO: C29.1 TP8.1(TP) U1.G9
TL_DDM: J58.2 R53.2
TL_DDP: J58.4 R55.2
TL_DM: J58.6 R47.2
TL_DMIC: C59.1 C60.1 C61.1 C62.1 R734.2 U10.6 U11.6 U12.2(SE) U12.6 U13.2(SE) U13.6
TL_DMIC0_CLK0: J64.4 R24.2 U10.4
TL_DMIC0_CLK1: J64.10 R26.2 U12.4
TL_DMIC0_DATA: J64.2 U10.5 U12.5
TL_DMIC1_CLK0: J64.8 R25.2 U11.4
TL_DMIC1_CLK1: J64.12 R27.2 U13.4
TL_DMIC1_DATA: J64.6 U11.5 U13.5
TL_DP: J58.8 R48.2
TL_EMMC1V8: C21.1 C427.1 C428.1 C470.1 R599.1 R601.1 R602.1 R603.1 R604.1 R605.1 R606.1 R607.1 R608.1 R661.1 R721.1 SW18.7 U55.5 U56.C6 U56.M4 U56.N4 U56.P3 U56.P5
TL_EMMC3V3: C429.1 C430.1 C468.1 C469.1 R715.1 U54.5 U56.E6 U56.F5 U56.J10 U56.K9
TL_EMMCCK: J62.2 R666.1
TL_EMMCCMD: J62.4 R599.2 U56.M5
TL_EMMCD0: J62.14 R601.2 U56.A3
TL_EMMCD1: J62.18 R602.2 U56.A4
TL_EMMCD2: J62.22 R603.2 U56.A5
TL_EMMCD3: J62.10 R604.2 U56.B2
TL_EMMCD4: J62.12 R605.2 U56.B3
TL_EMMCD5: J62.16 R606.2 U56.B4
TL_EMMCD6: J62.20 R607.2 U56.B5
TL_EMMCD7: J62.24 R608.2 U56.B6
TL_EMMCDS: J62.8 U56.H5
TL_EMMCRSTN: J62.6 R661.2 U56.K5
TL_LED1: R728.1 SW26.6
TL_LED2: R727.1 SW26.1
TL_LED3: Q2.1 R743.1 SW18.9
TL_LED4: Q3.1 R742.1 SW18.12
TL_LED5: R725.1 SW25.6
TL_MAX: L11.1 R50.1 R713.2
TL_MICBIASA1: SW8.7 SW9.7 SW10.7 SW11.7 U1.N6
TL_PA0: J62.1 U1.B7
TL_PA1: J62.3 U1.B6
TL_PA2: J62.9 U1.A6
TL_PA3: J3.6 R745.1 U1.B5
TL_PA4: J3.10 R744.1 U1.A5
TL_PA5: J3.8 SW23.1 U1.B4
TL_PA6: J3.14 SW24.1 U1.B3
TL_PA7: J70.4 U1.A4
TL_PB0: J62.19 U1.E2
TL_PB1: J4.6 SW20.1 U1.E1
TL_PB2: J4.4 SW21.1 U1.D2
TL_PB3: SW26.5 U1.D1
TL_PB4: SW26.2 U1.C2
TL_PB5: SW25.5 U1.C1
TL_PB5_EMMC: J62.7 SW25.4
TL_PB6: J62.5 SW17.3 U1.B2
TL_PB7: J62.17 U1.B1
TL_PC0: J62.11 U1.A3
TL_PC1: J62.13 U1.A2
TL_PC6: J62.15 U1.A1
TL_PF0: J58.1 U1.F1
TL_PF1: J58.3 U1.F2
TL_PF2: J58.5 U1.G1
TL_PF3: J58.7 U1.H1
TL_PF4: J62.21 U1.G2
TL_PF5: J62.23 U1.H2
TL_PG0: C472.2 U1.F8
TL_PG1: C472.1 U1.G8
TL_PG2: C471.2 U1.K8
TL_PG3: C471.1 U1.L8
TL_PG4: C473.1 C475.2 TP5.1 U1.M8
TL_PG5: C473.2 C474.1 TP7.1 U1.N8
TL_PG6: J70.5 U1.N7
TL_PI0: SW18.1 SW18.2 U1.E4
TL_PI0_P: C476.1 R718.1 SW18.10
TL_PI1: SW18.3 SW18.4 U1.F4
TL_PI1_N: C477.1 R718.2 SW18.11
TL_PI2: J64.1 U1.G4
TL_PI3: J64.5 U1.H6
TL_PI4: J64.7 J64.11 U1.J6
TL_PI5: J64.3 J64.9 U1.K6
TL_RST: C8.1 SW1.1 U1.C9
TL_SPK_LOUT: J57.8 R690.2
TL_SPK_ROUT: J57.3(R) R38.2
TL_TDI: J4.12 SW26.3
TL_TDO: J4.11 SW26.4
TL_VBAT: C12.1 J70.12 U1.K9
TL_VBAT_3V3: C92.1 C93.1 J70.8 U21.5
TL_VBAT_SIMO: C28.1 C113.1 J70.10 U1.H8
TL_VBUS: C11.1 R45.2 U1.L9
TL_VDDAO: C25.1 C26.1 R739.1 U1.M2
TL_VDDIO1: C4.1 J4.7 R36.1 R730.2 R731.2 U1.N9
TL_VDDIO4: C27.1 R732.2 R733.2 U1.P8
TL_VDDIO5: C10.1 R736.1 R741.2 U1.C8
TL_VDDRF1: C6.1 R737.1 U1.D8
TL_VDDRF2: C5.1 R735.2 U1.E8
TL_VIN: C15.1 C19.1 D1.A D10.A J70.1 J70.7 J70.9 J70.11 R713.1 U54.1 U54.3 U55.1 U55.3
TL_XTALM: C36.2 U1.A8 Y2.1
TL_XTALP: C35.2 U1.A7(XTAL_P) Y2.3
N20536109: L5.2 R43.2
N20536111: L6.2 R44.2
N20574830: C48.1 R16.2 U6.4(VDD)
N20574981: C47.1 R19.2 U7.4(VDD)
N20575273: R17.1 SW11.13
N20575330: R18.1 SW10.13
N20575385: R11.1 SW9.13
N20575656: C40.1 R8.2 U3.4(VDD)
N20677576: C39.1 R10.2 U2.4(VDD)
N20677726: R9.1 SW8.13
N20851990: C72.1 R39.1 R668.2 U53.14
N20851994: C72.2 R38.1 R39.2 U53.12
N20852024: C73.1 C460.1 C461.1 L11.2 U53.1 U53.9 U53.13
N20852182: C462.2 R668.1
N20852188: C71.1 U53.11
N20852219: C463.2 R30.1
N20852229: R30.2 R31.2 U53.15
N20852235: C70.1 U53.2
N20852237: C70.2 U53.4
N20852263: R687.2 R688.2 U53.7
N20852308: C464.2 R688.1
N20852314: C69.1 U53.5
N20852351: C465.2 R689.1
N20852353: C467.1 R689.2 R692.1 U53.8
N20852359: C467.2 R690.1 R692.2 U53.10
N20852392: C466.1 R50.2 R712.1 SP5.1 U53.16(\\S\H\D\N\)
N20909763: R715.2 R717.1 U54.4
N20909880: R721.2 R723.1 U55.4
N20909918: R723.2 R724.1
N20915858: C431.1 C432.1 U56.C2
N20915988: R666.2 U56.M6
N20942233: R736.2 R737.2 R738.2 R739.2 R740.2
N20953978: J22.2 R53.1
N20953991: J22.3 R55.1
N20954081: J21.2 R47.1
N20954094: J21.3 R48.1
N20958641: L3.1 U1.H9
N20958643: L3.2 U1.J9
N20958733: C16.1 C17.1 U1.J2
N20958777: C13.1 U1.L2
N20959069: C24.1 U1.N4
N20968251: D8.A R727.2
N20968303: D9.A R728.2
N20971815: D10.C(CATHODE) R729.1
N20971817: Q3.3 R729.2
N20971901: D1.C(CATHODE) R5.1
N20971903: Q2.3 R5.2
N20984994: R35.2 SW17.1
N20985013: R36.2 SW17.4
N20986499: D6.A R725.2
N210114041: D12.A R745.2
N210114121: D11.A R744.2

Pads without a net: J3 1 4 12; J4 1 2 10; J57 1 4 5 7; J70 3; SW14 1 4 5 8; SW15 1 4 5 8; SW17 2 5 6 7 8; SW18 5; SW25 1 2 3; U4 1 4; U5 1 4; U8 1 4; U9 1 4; U17 1 4; U18 1 4; U21 4; U56 A1 A2 A7 A8 A9 A10 A11 A12 A13 A14 B1 B7 B8 B9 B10 B11 B12 B13 B14 C1 C3 C5 C7 C8 C9 C10 C11 C12 C13 C14 D1 D2 D3 D4 D12 D13 D14 E1 E2 E3 E5 E8 E9 E10 E12 E13 E14 F1 F2 F3 F10 F12 F13 F14 G1 G2 G3 G10 G12 G13 G14 H1 H2 H3 H12 H13 H14 J1 J2 J3 J12 J13 J14 K1 K2 K3 K6 K7 K10 K12 K13 K14 L1 L2 L3 L12 L13 L14 M1 M2 M3 M7 M8 M9 M10 M11 M12 M13 M14 N1 N3 N6 N7 N8 N9 N10 N11 N12 N13 N14 P1 P2 P7 P8 P9 P10 P11 P12 P13 P14

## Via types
v1: diameter 0.5, hole 0.3, TOP to BOTTOM, 1890 vias
v2: diameter 0.24, hole 0.12, TOP to BOTTOM, 61 vias

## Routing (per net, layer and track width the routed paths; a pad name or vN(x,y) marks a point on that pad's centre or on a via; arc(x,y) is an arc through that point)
GND: length 106.4
  TOP w0.15: D8.C v1(25.5,71.4) ; 101.3,22.2 102.25,22.2 ; U1.K2 61.7,86.15 61.55,86.3 61.45,86.3 ; U56.E7 54.35,46.85 v1(54.5,47) ; C2.1 v1(56.41,92.5) ; U56.P4 v1(52.85,41.55) ; Q3.2 38.09,9.19 v1(38.2,9.3) ; v1(54.29,41.53) 54.3,41.53 54.3,41.6 54.22,41.67 54.19,41.67 53.98,41.89 53.98,41.92 U56.P6 ; v1(54.2,49.1) 53.85,48.75 U56.A6 ; D9.C v1(35,72.1) ; U56.J5 53.75,44.55 54,44.8 v1(54,45.3) 53.75,45.55 U56.G5 ; v1(33.7,10.1) 33.68,10.08 Q2.2 ; 103.8,23.4 103,23.4 ; U56.H10 v1(56.33,45.05) ; R743.2 v1(40.9,7.3) ; R742.2 v1(41.9,7.3) ; C4.2 v1(69.1,89.2)
  TOP w0.2: v1(66.82,87.8) 66.8,87.8 66.8,87.9 66.2,87.9 ; v1(66.83,89.28) 66.83,89.23 66.8,89.23 66.8,89.2 66.2,89.2 ; C12.2 v1(64.65,90.31) ; C11.2 v1(67.22,90.35) ; U1.N3 v2(62.9,85.9) ; R711.1 v1(58.5,31.3) ; 66.2,87.1 v1(66.8,87.1)
  TOP w0.5: v1(58.3,92.5) v1(58.3,90.2) ; v1(23.36,88.94) J3.7 v1(24.95,88.05) ; J3.11 v1(23.56,83.86) ; J3.11 v1(24.95,84.75) ; J3.11 v1(24.95,82.95) ; J3.9 v1(24.95,85.55) ; J3.9 v1(23.4,86.4) ; J3.9 v1(24.95,87.25) ; SW24.2 v1(8.74,96.54) ; v1(30.1,87.4) 30.1,86.7 30.4,86.4 J4.3 ; J4.9 v1(30.95,95.05) ; SW23.2 v1(8.84,91.54) ; J4.5 v1(30.95,87.95) ; v1(9.3,43) J21.4 ; SW20.2 v1(8.86,86.54) ; v1(23.52,81.32) J3.13 v1(24.95,82.25) ; SW21.2 v1(8.84,81.54)
  GND w0.15: v2(58.5,88.3) 58.6,88.3 58.85,88.05 58.85,87.75 ; 58.85,87.75 58.85,87.64 58.76,87.54 ; 58.85,87.75 59.3,87.3 v2(59.4,87.3) v2(59.9,87.3) 60.1,87.3 60.4,87.6
  GND w0.2: 60.3,87.9 60.1,87.9 ; 60.3,87.9 60.5,87.9 ; 60.3,87.9 60.1,87.7 ; 60.1,87.9 59.7,87.9 59.9,87.7 60.1,87.9 ; 60.5,87.9 60.3,87.7 ; 60.5,87.9 60.7,87.9 ; 61.9,87.9 62.1,87.9 ; 61.9,87.9 62.2,87.6 ; 61.9,87.9 60.7,87.9 ; 62.1,87.9 62.3,87.9 62.5,87.7 ; 62.1,87.9 62.4,87.6 ; 60.4,87.6 60.7,87.9
  POWER w0.15: 60.5,80 60.6,79.9 61.6,79.9 61.7,79.8 ; 56.7,81.3 56.7,82.1 ; 55.8,81.3 55.8,81.45 55.75,81.5 55.75,81.85 55.7,81.9 ; 58.2,80.3 58.9,80.3 ; v1(58.42,82.48) 58.42,82.49 58.9,82.96
  BOTTOM w0.15: C10.2 v1(56.3,87.6) ; v1(56.41,92.5) v1(58.3,92.5) ; v1(61.2,82.71) 61.2,82.8 61.6,83.2 C17.2 ; 65.4,86.2 C33.2 65.4,87 66.7,87 v1(66.8,87.1) 66.8,87.8 v1(66.82,87.8) ; 37.5,60.1 34,63.6 34,77.3 35.9,79.2 56.1,79.2 57.47,80.57 57.47,81.53 v1(58.42,82.48) ; C429.2 v1(55.3,45.6) ; v1(63.12,82.68) 63.1,82.68 63.1,82.8 63.4,83.1 63.4,83.3
  BOTTOM w0.5: v1(80.38,25.09) 80.31,25.09 v1(78.37,23.15)
  vias: v1(0.6,99.4) v1(0.6,97.8) v1(0.6,95.6) v1(0.6,93.3) v1(0.6,91.3) v1(0.6,89.1) v1(0.6,86.1) v1(0.6,82.8) v1(0.6,79.9) v1(0.6,75.8) v1(0.6,72) v1(0.6,58.9) v1(0.6,56.6) v1(0.6,50.8) v1(0.6,45.2) v1(0.6,42.4) v1(0.6,36.1) v1(0.6,32.7) v1(0.6,28.6) v1(0.6,23.9) v1(0.6,18.8) v1(0.6,14.6) v1(0.6,9) v1(0.6,4.7) v1(0.6,0.6) v1(0.7,68.1) v1(0.7,64.9) v1(1.7,60.6) v1(1.7,54.9) v1(1.7,49.8) v1(1.7,46.7) v1(1.7,40.9) v1(1.7,37.8) v1(1.8,63.7) v1(1.8,51.6) v1(2.3,23) v1(2.55,18.7) v1(2.45,16.2) v1(3.2,62.1) v1(3.2,39.4) v1(3.4,28.5) v1(3.55,25.8) v1(3.5,14.8) v1(4,0.6) v1(4.2,32.6) v1(4.2,31) v1(4.15,20.8) v1(4.2,12.6) v1(4.2,9.3) v1(4.4,72.9) v1(4.55,16.3) v1(4.6,99.4) v1(4.8,90.1) v1(4.8,86.1) v1(5,81) v1(5.5,23.45) v1(5.7,74.5) v1(5.85,18.9) v1(5.9,68) v1(5.95,16.65) v1(6,13.75) v1(6.3,62.1) v1(7.1,26.85) v1(7.15,9.85) v1(7.35,21.35) v1(7.6,40.9) v1(7.7,71.7) v1(7.7,63.7) v1(7.7,60.6) v1(7.7,54.9) v1(7.7,49.8) v1(7.7,37.8) v1(7.8,51.6) v1(7.9,6.3) v1(8.25,25.5) v1(8.2,18.9) v1(8.2,15.3) v1(8.2,12.5) v1(8.8,33) v1(8.8,29) v1(8.8,9) v1(9,0.6) v1(9.1,48.4) v1(9.2,62.1) v1(9.2,39.5) v1(9.3,56.9) v1(9.3,56.1) v1(9.3,42.2) v1(9.35,24.05) v1(9.6,99.4) v1(9.7,47.6) v1(9.8,3.8) v1(9.9,32.2) v1(9.95,9.75) v1(10,88.7) v1(10.1,78.5) v1(10.3,84) v1(10.4,68.5) v1(10.4,48.3) v1(10.4,14.9) v1(10.5,62.3) v1(10.5,43) v1(10.5,29.9) v1(10.6,18.65) v1(10.7,21.2) v1(10.65,6.15) v1(10.9,56.9) v1(11.1,47.6) v1(11.1,10.8) v1(11.2,93.8) v1(11.3,27.6) v1(11.6,45.4) v1(11.6,25.2) v1(11.7,54.8) v1(11.7,52.8) v1(11.7,50.6) v1(11.7,48.4) v1(11.7,46.9) v1(11.7,43.2) v1(11.82,59.1) v1(11.95,65.6) v1(11.95,37) v1(11.9,32.15) v1(12,76.7) v1(12.1,20.9) v1(12.1,18.2) v1(12.1,12.05) v1(12.2,57.4) v1(12.35,40.2) v1(12.6,29.8) v1(12.7,56.7) v1(12.65,42.1) v1(12.65,7.95) v1(12.9,93.8) v1(13.03,58.3) v1(13,55) v1(13,53.9) v1(13,52.4) v1(13,50.6) v1(13,48.6) v1(13,47.2) v1(13,45.1) v1(13,43.9) v1(13.7,13.6) v1(13.7,6.2) v1(13.9,17.35) v1(14,47.7) v1(14,0.6) v1(14.1,26.5) v1(14.1,23.1) v1(14.1,20.05) v1(14.2,56.3) v1(14.3,3.6) v1(14.6,99.4) v1(14.55,29.85) v1(14.75,32.15) v1(15,10.15) v1(15.2,73.6) v1(15.4,93.9) v1(15.5,48.7) v1(15.5,46.7) v1(15.55,15.35) v1(15.7,41.3) v1(15.75,36.85) v1(15.8,28.3) v1(15.9,24.5) v1(15.9,20.9) v1(16.7,12.4) v1(16.9,69.4) v1(17.1,47.7) v1(17.3,41.15) v1(17.5,27.3) v1(17.5,8.6) v1(17.55,24.65) v1(17.55,21) v1(17.7,43.8) v1(17.8,17.3) v1(18.15,48.95) v1(18.5,6.2) v1(18.55,75) v1(18.6,12.6) v1(19,0.6) v1(19.2,44.65) v1(19.2,43.45) v1(19.4,42) v1(19.6,99.4) v1(19.55,19.35) v1(19.6,16.5) v1(19.8,23.5) v1(20.15,31.35) v1(20.05,25.15) v1(20.2,72.7) v1(20.3,85.8) v1(20.3,83.3) v1(20.3,81.3) v1(20.6,11.4) v1(20.7,93.5) v1(20.7,89.8) v1(20.7,8.8) v1(20.7,3.8) v1(20.8,87.7) v1(20.8,15.25) v1(20.9,33.25) v1(21.2,97.5) v1(21.2,41.35) v1(21.3,44) v1(21.35,46.45) v1(21.45,28.7) v1(21.4,19.1) v1(21.6,21.2) v1(22,76) v1(22,56.1) v1(22.22,70.49) v1(22.2,41.3) v1(22.4,73.8) v1(22.4,32.6) v1(22.4,31) v1(22.4,29.3) v1(22.6,96.4) v1(22.7,46.5) v1(22.7,44) v1(22.8,22.65) v1(22.8,6.2) v1(23,68.7) v1(23.2,94.1) v1(23.2,91.7) v1(23.2,85.3) v1(23.2,82.6) v1(23.3,87.6) v1(23.3,17.3) v1(23.8,27.1) v1(23.8,15.45) v1(23.9,20.25) v1(24,0.6) v1(24.1,25) v1(24.2,12.7) v1(24.2,9.3) v1(24.6,99.4) v1(24.6,22.8) v1(24.8,97.8) v1(24.81,60.79) v1(25,51.1) v1(25,46.8) v1(25,41.7) v1(25,18.15) v1(25.12,62.6) v1(25.2,95.1) v1(25.2,67.4) v1(25.5,56.1) v1(25.7,77.8) v1(25.7,50.5) v1(25.7,46.1) v1(25.7,41.1) v1(25.85,60.05) v1(25.8,3.8) v1(25.9,26.8) v1(26.15,24.95) v1(26.15,16.6) v1(26.31,65.19) v1(26.4,91.6) v1(26.38,62) v1(26.5,20.9) v1(27.1,69.2) v1(27.25,64.35) v1(27.5,18.3) v1(27.6,75.7) v1(27.7,57.8) v1(27.8,78.2) v1(27.8,60.3) v1(27.8,14.8) v1(28,63) v1(28.1,54.7) v1(28.25,26.45) v1(28.3,23.6) v1(28.3,12.5) v1(28.35,24.95) v1(28.4,22.4) v1(28.5,51.7) v1(28.5,47.4) v1(28.5,42.3) v1(28.8,45) v1(28.8,9) v1(28.9,33) v1(28.9,29) v1(29,0.6) v1(29.2,67.1) v1(29.2,3.9) v1(29.3,6.4) v1(29.4,47.4) v1(29.4,42.3) v1(29.5,51.7) v1(29.6,99.4) v1(29.9,31.75) v1(30.57,76.64) v1(30.6,69.6) v1(30.8,65.2) v1(30.8,40.3) v1(30.8,9.8) v1(30.85,24.95) v1(31,17.3) v1(31,13.5) v1(31.15,30.7) v1(31.4,20.1) v1(31.8,50.5) v1(31.8,40.3) v1(32.2,67.3) v1(32.5,94.1) v1(32.5,89) v1(32.5,86.5) v1(32.5,65.1) v1(32.5,51.2) v1(32.6,41) v1(32.7,46.2) v1(32.7,10.9) v1(32.7,8.2) v1(32.8,15.5) v1(32.9,83.8) v1(32.9,76.9) v1(33,90.9) v1(33,5.2) v1(33.1,95.35) v1(33.1,18.5) v1(33.25,89.35) v1(33.25,87.5) v1(33.2,58.4) v1(33.2,51.6) v1(33.2,41.7) v1(33.3,46.8) v1(33.5,61) v1(33.5,13.8) v1(33.7,8.3) v1(33.9,41.8) v1(34.05,30.8) v1(34,20.4) v1(34,0.6) v1(34.5,47.4) v1(34.6,99.4) v1(34.6,12.6) v1(34.6,11) v1(34.7,67.1) v1(34.7,45.5) v1(34.8,65.7) v1(34.8,16.2) v1(34.95,82.5) v1(35.01,73.79) v1(35.15,91.7) v1(35.1,89.35) v1(35.1,40.05) v1(35.15,35.25) v1(35.1,34.4) v1(35.1,33.6) v1(35.1,32.7) v1(35.1,31.9) v1(35.2,94.1) v1(35.25,31.05) v1(35.35,18.1) v1(35.4,14) v1(35.54,78.16) v1(35.7,70.1) v1(35.8,57.5) v1(35.9,87.65) v1(36.15,85.1) v1(36.1,55) v1(36.1,53.1) v1(36.2,76.1) v1(36.23,73.81) v1(36.2,71.6) v1(36.2,44.25) v1(36.3,15.9) v1(36.45,40.35) v1(36.6,69) v1(36.6,7) v1(36.6,5.6) v1(36.8,46.95) v1(36.8,11.7) v1(36.8,10.5) v1(37.05,82.5) v1(37.2,42.5) v1(37.2,41.1) v1(37.3,78) v1(37.3,60.2) v1(37.4,87.6) v1(37.5,72) v1(37.5,8.3) v1(37.6,69.4) v1(37.7,64.6) v1(37.85,85.15) v1(37.95,11.9) v1(38.1,80.45) v1(38.2,62.5) v1(38.2,15.45) v1(38.2,13.6) v1(38.4,51.3) v1(38.6,60.8) v1(38.6,45.6) v1(38.8,69.4) v1(38.8,30.7) v1(38.8,18.2) v1(38.9,72.6) v1(38.9,33.3) v1(38.9,28.3) v1(39,87.6) v1(39,67.8) v1(39,0.6) v1(39.1,16.5) v1(39.2,78.6) v1(39.2,74.3) v1(39.2,20.4) v1(39.55,46.95) v1(39.6,99.4) v1(39.6,97.7) v1(39.6,95.75) v1(39.65,94.05) v1(39.6,82.5) v1(39.6,54.9) v1(39.6,44.3) v1(39.84,58.44) v1(39.85,85.1) v1(39.85,80.5) v1(39.9,42.15) v1(39.9,30.7) v1(39.9,28.3) v1(40.25,91.25) v1(40.2,45.6) v1(40.2,14.2) v1(40.3,75.4) v1(40.5,67.8) v1(40.5,19.5) v1(40.6,33.4) v1(40.6,11.6) v1(40.7,73.9) v1(40.7,72.7) v1(40.7,49.9) v1(40.7,16.6) v1(40.8,30.7) v1(40.8,28.2) v1(40.85,87.15) v1(40.85,42.55) v1(41.1,70.7) v1(41.1,66.4) v1(41.1,62.2) v1(41.2,84.4) v1(41.2,60.5) v1(41.3,40.6) v1(41.4,83.2) v1(41.4,59.2) v1(41.55,91.75) v1(41.5,56.5) v1(41.6,97.75) v1(41.65,96.05) v1(41.6,78.6) v1(41.7,93.45) v1(41.7,34.55) v1(41.8,75.3) v1(41.8,30.8) v1(41.9,85.7) v1(41.85,80.5) v1(42.3,19.7) v1(42.4,84.8) v1(42.4,83.6) v1(42.4,82.5) v1(42.6,15.7) v1(42.7,10.5) v1(42.7,6.3) v1(42.7,3.2) v1(42.75,94.45) v1(42.8,67.9) v1(42.85,91.65) v1(42.9,54.2) v1(43,88.8) v1(43,78.1) v1(43,33.2) v1(43,30.6) v1(43.1,42.3) v1(43.3,48.3) v1(43.3,45.4) v1(43.3,40.5) v1(43.4,95.7) v1(43.4,28.4) v1(43.4,24.85) v1(43.5,69.2) v1(43.5,22.6) v1(43.55,20.4) v1(43.65,97.65) v1(43.65,93.05) v1(43.6,77.1) v1(43.7,73.3) v1(43.7,71.7) v1(43.7,59) v1(43.8,66.3) v1(43.8,61) v1(43.9,62.8) v1(43.85,34.55) v1(44,0.6) v1(44.2,68.2) v1(44.2,30.75) v1(44.3,87.7) v1(44.3,86.2) v1(44.6,99.4) v1(44.6,89.3) v1(44.6,57.4) v1(44.6,26.1) v1(44.8,78.3) v1(44.8,28.3) v1(44.9,94.45) v1(44.9,42.3) v1(44.9,33.2) v1(45.3,40.5) v1(45.3,14.3) v1(45.3,7.9) v1(45.4,46.7) v1(45.5,92) v1(45.6,97.65) v1(45.7,25.3) v1(45.7,17.8) v1(45.8,86.2) v1(45.8,22.5) v1(45.9,93.5) v1(45.95,88.1) v1(46,68.9) v1(46,56) v1(46.15,19.9) v1(46.2,83.3) v1(46.2,62.4) v1(46.2,61) v1(46.2,59.3) v1(46.35,34.6) v1(46.6,45.5) v1(46.7,66.6) v1(46.8,96.4) v1(46.8,58) v1(46.8,30.8) v1(46.85,86.9) v1(47,67.6) v1(47.1,85) v1(47.1,42.3) v1(47.1,33.2) v1(47.2,26.1) v1(47.26,82.34) v1(47.3,40.5) v1(47.6,81.1) v1(47.6,57) v1(47.6,49.8) v1(47.6,24.7) v1(47.7,17.4) v1(47.8,68) v1(47.8,28.4) v1(47.91,82.99) v1(47.9,12.6) v1(47.9,8.6) v1(48,86) v1(48,69) v1(48,52.3) v1(48.05,19.35) v1(48.1,81.5) v1(48.25,30.85) v1(48.35,97.6) v1(48.5,50.5) v1(48.6,91.4) v1(48.6,66.3) v1(48.6,48.6) v1(48.7,82) v1(48.7,64.7) v1(48.8,94.5) v1(48.8,89.55) v1(48.8,43.1) v1(48.8,34.6) v1(48.9,84.4) v1(49,33.2) v1(49,0.6) v1(49.3,40.6) v1(49.4,49.4) v1(49.5,47.5) v1(49.5,28.1) v1(49.6,99.4) v1(49.6,46.7) v1(49.85,89.9) v1(50.1,48.1) v1(50.1,33.3) v1(50.3,96.1) v1(50.3,68.7) v1(50.5,82.4) v1(50.5,34.9) v1(50.6,74.9) v1(50.56,40.06) v1(50.6,31) v1(50.6,26.6) v1(50.7,77.3) v1(50.9,88.6) v1(50.85,84.15) v1(51,29.6) v1(51.3,72.1) v1(51.4,92.7) v1(51.8,97.1) v1(51.8,40) v1(51.9,28) v1(52,68.7) v1(52.1,89.3) v1(52.1,39.4) v1(52.1,32.5) v1(52.4,31.1) v1(52.6,88.2) v1(52.9,93.8) v1(53,83.4) v1(53.3,84.9) v1(53.3,29.4) v1(53.7,99.4) v1(53.7,97.4) v1(53.7,95.9) v1(53.8,88.5) v1(53.8,32.4) v1(53.9,69.1) v1(54.1,91.8) v1(54.1,34.4) v1(54.3,85.9) v1(54.5,95.5) v1(54.6,30.5) v1(54.7,92.6) v1(54.8,33.4) v1(54.9,41.2) v1(55.1,93.9) v1(55.3,40) v1(55.6,95.5) v1(55.6,69.1) v1(56,31.7) v1(56.1,90.4) v1(56.3,91.5) v1(56.4,94.4) v1(56.5,40.1) v1(56.8,41.3) v1(56.9,92.1) v1(56.9,91) v1(56.9,52.1) v1(57,50.2) v1(57.1,89.1) v1(57.3,40.7) v1(57.6,69) v1(58,30.8) v1(58.2,93.4) v1(58.25,91.75) v1(58.25,91.1) v1(58.7,52.2) v1(58.8,50.2) v1(58.8,40.2) v1(58.9,81.3) v1(59.05,94.8) v1(59,30.8) v1(59.1,47.8) v1(59.2,54.3) v1(59.2,44.8) v1(59.4,42.2) v1(59.5,79) v1(59.6,95.5) v1(60.6,95.5) v1(60.6,47.4) v1(60.6,45.4) v1(60.9,66.5) v1(60.9,52.2) v1(60.9,40.1) v1(61,50.2) v1(61.6,99.4) v1(61.6,96.1) v1(61.6,78.95) v1(61.7,42.2) v1(62.2,54.7) v1(62.6,98.6) v1(62.8,40.2) v1(63,68.6) v1(63,66.6) v1(63.1,49) v1(63.3,47.8) v1(63.3,42.2) v1(63.5,56) v1(63.6,82.25) v1(64.05,81.8) v1(64.1,96.1) v1(64.1,31.1) v1(64.6,99.4) v1(64.6,49) v1(64.6,47.9) v1(64.7,57.3) v1(65.1,16.4) v1(65.1,10.1) v1(65.1,8.4) v1(65.1,4.1) v1(65.1,0.7) v1(65.2,68.6) v1(65.2,26.6) v1(65.2,22.1) v1(65.2,20.6) v1(65.2,18.4) v1(65.2,14.5) v1(65.2,12.5) v1(65.2,6.3) v1(65.3,66.6) v1(65.3,54.4) v1(65.3,40.1) v1(65.3,29.9) v1(65.4,96.6) v1(65.4,28.6) v1(65.4,23.9) v1(65.8,1.7) v1(66.1,32) v1(66.2,58.8) v1(66.3,93.5) v1(66.3,40.1) v1(66.5,82.2) v1(66.8,26.5) v1(66.8,21.3) v1(66.9,45.2) v1(66.9,24.6) v1(66.9,6.4) v1(67,96.6) v1(67.1,52.8) v1(67.1,51.3) v1(67.2,49.1) v1(67.2,30.3) v1(67.2,17.5) v1(67.3,56.6) v1(67.3,47.1) v1(67.4,19.5) v1(67.4,2.7) v1(67.5,66.6) v1(67.5,60.4) v1(67.6,93.5) v1(67.6,7.5) v1(67.7,80.9) v1(67.8,55.1) v1(67.9,28.4) v1(68,96.6) v1(68,22.7) v1(68.1,68.6) v1(68.25,82.4) v1(68.2,6.5) v1(68.4,16.5) v1(68.5,93.5) v1(68.5,26.1) v1(68.5,20.8) v1(68.6,99.4) v1(68.7,19.3) v1(68.7,12.8) v1(68.7,10.1) v1(68.7,8.5) v1(68.8,96.6) v1(68.8,41.8) v1(68.8,15.1) v1(68.9,62.1) v1(69,17.5) v1(69,0.6) v1(69.1,70.9) v1(69.2,68.4) v1(69.2,56.6) v1(69.2,54.2) v1(69.2,30.7) v1(69.2,21.4) v1(69.3,58.9) v1(69.3,1.7) v1(69.5,48.5) v1(69.5,7.8) v1(69.6,20.1) v1(69.7,16.7) v1(69.8,93.5) v1(69.8,86.6) v1(69.8,14.9) v1(69.8,13.2) v1(69.8,11.2) v1(69.8,9.3) v1(70,67.3) v1(70.1,96.7) v1(70.1,32.1) v1(70.3,42.9) v1(70.3,20.6) v1(70.4,99.4) v1(70.5,25.2) v1(70.6,7.5) v1(70.6,5.5) v1(70.6,2.7) v1(70.6,0.8) v1(70.9,10.4) v1(71,16.3) v1(71,12.7) v1(71.1,14.1) v1(71.35,85.85) v1(71.35,85) v1(71.3,62) v1(71.4,64.3) v1(71.5,59.3) v1(71.5,51.1) v1(71.5,44.2) v1(71.5,20.7) v1(71.6,56.6) v1(71.6,54.2) v1(71.6,52.4) v1(71.6,48.6) v1(71.6,21.3) v1(71.7,46.4) v1(72.05,83.3) v1(72.1,99.4) v1(72.4,96.7) v1(72.4,16.7) v1(72.4,14.6) v1(72.45,92.25) v1(72.5,6.8) v1(72.6,87.4) v1(72.6,25.3) v1(72.6,12.5) v1(72.6,10.5) v1(72.7,84.6) v1(72.9,77.6) v1(72.9,35.2) v1(73,31.7) v1(73,5.1) v1(73.75,91) v1(73.85,80.35) v1(73.8,10.5) v1(73.9,16.5) v1(73.9,12.5) v1(73.95,84.15) v1(73.95,82.2) v1(73.95,76.55) v1(74,0.6) v1(74.2,30.5) v1(74.3,44.3) v1(74.3,36.6) v1(74.6,99.4) v1(74.6,96.7) v1(74.6,14.6) v1(74.7,6.9) v1(74.8,28.1) v1(74.8,26.2) v1(75,89.25) v1(75,69.9) v1(75.1,87.7) v1(75.1,72.1) v1(75.2,78.95) v1(75.15,77.15) v1(75.3,34.4) v1(75.55,80.55) v1(75.5,5) v1(75.6,16.2) v1(75.6,14.2) v1(75.7,17.6) v1(75.7,12.1) v1(75.7,10.8) v1(75.8,74.7) v1(75.8,69) v1(75.8,38.1) v1(75.95,82.15) v1(76,76.3) v1(76,71.4) v1(76.1,66.2) v1(76.1,62.9) v1(76.1,59.5) v1(76.1,56.1) v1(76.1,52.8) v1(76.1,50.2) v1(76.2,21.3) v1(76.3,47.7) v1(76.6,35.7) v1(76.65,86.2) v1(76.8,39) v1(76.9,75.4) v1(76.9,18.1) v1(76.9,16.6) v1(76.9,15.1) v1(76.9,13.8) v1(76.9,12.4) v1(76.9,10.8) v1(77.05,77.15) v1(77,47) v1(77.2,7) v1(77.3,22.3) v1(77.5,78.6) v1(77.5,73) v1(77.6,80.5) v1(77.7,74.6) v1(77.8,37) v1(77.9,20.7) v1(78.1,29.5) v1(78.1,18.7) v1(78.1,5.1) v1(78.15,84.65) v1(78.2,69.9) v1(78.2,61) v1(78.2,57.9) v1(78.2,51.6) v1(78.2,32.6) v1(78.2,26.2) v1(78.2,24) v1(78.35,79.75) v1(78.35,75.8) v1(78.35,72) v1(78.35,70.85) v1(78.3,68.3) v1(78.3,64.6) v1(78.3,54.4) v1(78.3,49) v1(78.3,44.6) v1(78.3,40.1) v1(78.4,42.6) v1(78.4,41.4) v1(78.4,12) v1(78.5,17.2) v1(78.9,21.6) v1(78.9,13.6) v1(79,0.6) v1(79.1,15.9) v1(79.3,9.4) v1(79.5,7.1) v1(79.7,18.7) v1(79.8,83) v1(79.9,23.4) v1(80.2,20.2) v1(80.2,12) v1(80.2,5.1) v1(80.3,21.3) v1(80.4,44.6) v1(80.4,42.7) v1(80.4,40.2) v1(80.4,37.1) v1(80.4,33.5) v1(80.4,31) v1(80.4,28.9) v1(80.5,26.4) v1(80.7,22.5) v1(80.8,27.5) v1(80.9,32.2) v1(80.9,29.9) v1(81.1,9.4) v1(81.35,81.35) v1(81.3,74.85) v1(81.3,46.3) v1(81.4,80.3) v1(81.4,76.7) v1(81.4,70.9) v1(81.4,65.8) v1(81.4,58.3) v1(81.4,56) v1(81.4,41.9) v1(81.55,72.65) v1(81.5,68.4) v1(81.5,63.1) v1(81.5,51.2) v1(81.5,48.9) v1(81.5,23.8) v1(81.5,15.9) v1(81.6,21.6) v1(81.6,20) v1(81.7,17.3) v1(81.8,13.6) v1(81.8,12) v1(81.9,30.3) v1(81.9,25.4) v1(82,7.2) v1(82.1,39.1) v1(82.1,33) v1(82.25,71.9) v1(82.25,70.05) v1(82.4,5.1) v1(82.5,78.8) v1(82.65,77.35) v1(82.7,22.7) v1(82.7,18.7) v1(82.8,20.4) v1(82.9,71.3) v1(82.9,69.3) v1(82.9,68.3) v1(82.9,66.1) v1(82.9,62.8) v1(82.9,61.3) v1(82.9,58.2) v1(82.9,55.8) v1(82.9,51.6) v1(83,54.2) v1(83,1.7) v1(83.1,73.05) v1(83.35,74.7) v1(83.3,44.6) v1(83.3,13.6) v1(83.4,47.15) v1(83.4,17.2) v1(83.4,7.3) v1(83.5,49.3) v1(83.6,76.4) v1(83.6,19.7) v1(83.7,9.5) v1(83.9,23) v1(84,0.6) v1(84.1,37.2) v1(84.1,26.9) v1(84.1,21.2) v1(84.15,70) v1(84.2,68.6) v1(84.2,65.6) v1(84.2,63.2) v1(84.2,61.1) v1(84.2,59.5) v1(84.2,55.7) v1(84.2,40.7) v1(84.3,54.2) v1(84.3,51.4) v1(84.3,6.4) v1(84.4,57.9) v1(84.4,17.7) v1(84.5,32.8) v1(84.5,13.6) v1(84.7,16) v1(84.7,2.7) v1(84.8,50.2) v1(84.8,9.6) v1(84.9,7.6) v1(85,74.95) v1(85.05,73.05) v1(85,47.9) v1(85.1,43.1) v1(85.2,77.75) v1(85.3,17) v1(85.47,70.62) v1(85.55,56.9) v1(85.6,69.9) v1(85.6,62.95) v1(85.6,61.25) v1(85.6,6.6) v1(85.7,65.3) v1(85.65,64.55) v1(85.65,44.6) v1(85.8,24.6) v1(85.8,8.4) v1(86,52.7) v1(86,50.9) v1(86,48.6) v1(86,46.3) v1(86,39.1) v1(86.1,65.9) v1(86.1,58.75) v1(86.1,30.9) v1(86.2,21.3) v1(86.3,9.8) v1(86.4,74.6) v1(86.4,34.8) v1(86.4,20.2) v1(86.4,15.4) v1(86.4,13.5) v1(86.5,76.7) v1(86.5,71.6) v1(86.55,55.75) v1(86.5,7.5) v1(86.5,1.7) v1(86.8,78.7) v1(86.92,72.52) v1(87,16.9) v1(87.1,8.2) v1(87.2,57.6) v1(87.4,11.3) v1(87.4,9.7) v1(87.5,15.6) v1(87.5,14.4) v1(87.5,12.8) v1(87.6,74.95) v1(87.6,60.9) v1(87.6,40.6) v1(87.6,3.5) v1(87.7,72) v1(87.7,5.2) v1(87.8,67) v1(87.8,63.7) v1(87.9,67.8) v1(87.9,54.5) v1(88,44.9) v1(87.95,42.45) v1(88,25.8) v1(88,20.2) v1(88.1,37.4) v1(88.1,6.8) v1(88.2,21.3) v1(88.3,32.8) v1(88.4,46.7) v1(88.5,72.7) v1(88.45,49.7) v1(88.8,77.8) v1(88.8,58.75) v1(88.8,16.2) v1(88.9,14.9) v1(89,0.6) v1(89.1,13.5) v1(89.1,12.4) v1(89.2,74.6) v1(89.3,55.8) v1(89.3,11.1) v1(89.5,38.3) v1(89.5,20.2) v1(89.6,51.8) v1(89.6,43.3) v1(89.85,53.85) v1(89.8,45.1) v1(90,76.7) v1(90,20.9) v1(90.1,35.4) v1(90.2,63.85) v1(90.25,40.25) v1(90.2,5.2) v1(90.3,6.8) v1(90.4,30.9) v1(90.55,69) v1(90.6,61.6) v1(90.7,67) v1(90.7,13.5) v1(90.8,70.7) v1(90.9,75.2) v1(90.9,19.9) v1(90.9,11) v1(91,16.2) v1(91.1,3.8) v1(91.1,1.8) v1(91.2,78.7) v1(91.25,55.45) v1(91.15,46.65) v1(91.2,15) v1(91.3,59.9) v1(91.3,12.2) v1(91.4,57.6) v1(91.4,21.2) v1(91.6,25.6) v1(91.7,41.1) v1(91.7,33.7) v1(91.7,19.2) v1(91.8,22.9) v1(91.8,8) v1(91.9,5.7) v1(92,71.8) v1(92,43) v1(92.1,61.5) v1(92.1,50.75) v1(92.1,35.8) v1(92.25,37.9) v1(92.3,53.9) v1(92.3,28.9) v1(92.4,20.2) v1(92.6,63.75) v1(92.7,23.7) v1(92.7,17.8) v1(92.7,16.2) v1(92.7,14.2) v1(92.7,12.4) v1(92.7,10.8) v1(92.8,66.95) v1(93.1,71) v1(93.1,68.9) v1(93.1,21.6) v1(93.25,58.15) v1(93.2,32.2) v1(93.35,77.85) v1(93.3,73) v1(93.3,72.4) v1(93.3,39.4) v1(93.3,19.2) v1(93.5,6.9) v1(93.6,53.8) v1(93.6,41.2) v1(93.6,34.1) v1(93.6,25.4) v1(93.7,27.5) v1(93.7,26.4) v1(93.7,22.7) v1(93.7,5.1) v1(93.8,17.8) v1(93.8,16.6) v1(93.8,14.9) v1(93.8,13.4) v1(93.8,12.1) v1(93.8,10.9) v1(93.9,55.4) v1(94,0.6) v1(94.45,48.25) v1(94.5,31) v1(94.7,78.7) v1(94.7,35.5) v1(94.8,44.1) v1(95,63.7) v1(95,61.5) v1(94.95,59.35) v1(94.95,49.25) v1(95.05,47.4) v1(95.1,57.85) v1(95.1,55.55) v1(95.1,53.6) v1(95.1,51) v1(95.1,28.2) v1(95.3,71.1) v1(95.3,68.9) v1(95.4,30.3) v1(95.6,67) v1(95.6,22.6) v1(95.7,34.85) v1(95.7,11.2) v1(95.85,31.9) v1(95.8,9.5) v1(95.9,16.8) v1(95.9,5.8) v1(96,43.3) v1(96,24.9) v1(96,20.7) v1(96,18.8) v1(96.1,23.5) v1(96.2,11.4) v1(96.3,65.45) v1(96.3,40.85) v1(96.4,4) v1(96.5,7.6) v1(96.7,58.55) v1(96.7,55.35) v1(96.65,53.15) v1(96.65,51.05) v1(96.65,49.35) v1(96.75,57.15) v1(96.9,72.9) v1(97,68.5) v1(97.05,36.85) v1(97.1,15.1) v1(97.1,14.1) v1(97.1,11) v1(97.3,46.35) v1(97.5,78.7) v1(97.5,62.95) v1(97.7,71) v1(97.7,24) v1(97.7,20.5) v1(97.7,16.1) v1(97.75,64.35) v1(97.8,26.9) v1(97.8,25.8) v1(97.8,22.4) v1(97.8,17.7) v1(97.9,29.9) v1(97.95,57.35) v1(98.2,59.25) v1(98.2,55.5) v1(98.25,47.7) v1(98.2,39.35) v1(98.3,67) v1(98.35,32.7) v1(98.55,53.95) v1(98.55,51.5) v1(98.5,49.5) v1(98.5,43.3) v1(98.7,78) v1(98.7,11.1) v1(99,0.6) v1(99.1,61.65) v1(99.2,59.3) v1(99.15,57.35) v1(99.15,35.1) v1(99.45,45.85) v1(99.5,27.2) v1(99.6,29.1) v1(99.7,63) v1(99.8,41.2) v1(99.9,65.2) v1(99.9,43.1) v1(99.9,10.9) v1(100,50.5) v1(100,47.95) v1(100,3) v1(100.1,72.9) v1(100.1,68.8) v1(100.1,8.2) v1(100.2,78) v1(100.2,71.1) v1(100.15,59.25) v1(100.15,57.35) v1(100.4,26) v1(100.5,55.5) v1(100.45,52.6) v1(100.5,24.3) v1(100.65,37.35) v1(100.7,12.9) v1(100.8,40) v1(100.9,28.8) v1(101.2,67.1) v1(101.2,45.25) v1(101.2,35.1) v1(101.2,19.1) v1(101.35,53.95) v1(101.3,51.1) v1(101.8,7.9) v1(102.05,68.7) v1(102,23.9) v1(102.1,55.55) v1(102.25,66.95) v1(102.2,28.5) v1(102.4,33.2) v1(102.45,49.2) v1(102.5,39.9) v1(102.65,37.9) v1(102.8,34.2) v1(103,51.5) v1(103,35.4) v1(103.35,65.5) v1(103.4,36.5) v1(103.7,49.2) v1(103.7,33.2) v1(103.8,55.65) v1(104,0.6) v1(104.1,24.1) v1(104.2,36.3) v1(104.2,8) v1(104.3,37.4) v1(104.55,67.75) v1(104.55,66.45) v1(104.45,52.95) v1(104.6,34.6) v1(104.65,50.55) v1(104.7,39.9) v1(105,68.92) v1(105.1,44.45) v1(105.1,3.2) v1(105.2,33.3) v1(105.35,55.5) v1(105.3,37.6) v1(105.45,49.2) v1(105.7,78.8) v1(105.9,12.5) v1(106,40) v1(106.1,37.7) v1(106.1,21.7) v1(106.2,53.7) v1(106.5,8) v1(106.9,23.9) v1(106.95,55.4) v1(107.1,21.7) v1(107.2,53.7) v1(107.2,37.7) v1(107.9,44.4) v1(107.9,40) v1(108,8) v1(108.2,28.3) v1(108.7,37.6) v1(108.9,12.4) v1(109,69) v1(109,0.6) v1(109.1,3.3) v1(109.2,27.8) v1(109.9,39.4) v1(110,36.9) v1(110,6.6) v1(110.1,64.9) v1(110.1,59.7) v1(110.1,43.7) v1(110.1,32.9) v1(110.1,23.1) v1(110.1,16.9) v1(110.1,11.7) v1(110.2,67.6) v1(110.2,48.9) v1(110.2,27.6) v1(110.3,66.6) v1(110.4,54.6) v1(110.8,65.4) v1(110.8,63.4) v1(110.8,58.1) v1(110.8,47.5) v1(110.8,42) v1(110.8,31.5) v1(110.8,26.1) v1(110.8,24.4) v1(110.8,15.3) v1(110.8,10.1) v1(110.9,8.1) v1(111.8,29) v1(111.9,76.1) v1(112,78.6) v1(112,60.3) v1(111.95,44.9) v1(112.05,42.8) v1(112,27) v1(112.1,56.2) v1(112.15,58.55) v1(112.35,48.55) v1(112.3,32.8) v1(112.45,65.3) v1(112.6,53.8) v1(112.7,24.5) v1(112.7,8.2) v1(112.85,68.15) v1(112.75,66.5) v1(112.8,39.4) v1(112.9,57.6) v1(113.05,41.1) v1(113,23.2) v1(113.4,49.45) v1(113.4,6.5) v1(113.6,25.4) v1(113.65,69) v1(113.65,51.5) v1(113.8,38.9) v1(113.8,37.5) v1(113.8,33.7) v1(113.8,6.3) v1(113.9,66.3) v1(113.9,35.8) v1(114,0.6) v1(114.1,31.8) v1(114.25,56.15) v1(114.2,34.6) v1(114.5,76.2) v1(114.5,3.2) v1(114.6,78.6) v1(115,33.1) v1(115.1,74) v1(115.2,72.2) v1(115.2,70.9) v1(115.15,45.3) v1(115.3,8.6) v1(115.5,41.2) v1(115.5,27.8) v1(115.6,26.4) v1(115.6,23.1) v1(115.7,38.8) v1(115.7,29.7) v1(115.75,61.8) v1(115.75,57.6) v1(115.8,6.4) v1(115.9,59.8) v1(115.9,24.6) v1(116.5,12.8) v1(116.6,34.6) v1(116.6,13.7) v1(116.6,10.8) v1(116.7,36.9) v1(116.8,45.25) v1(116.8,38.6) v1(116.8,35.6) v1(117.05,56.15) v1(117.1,50.35) v1(117.1,6.6) v1(117.25,43.15) v1(117.2,8.1) v1(117.3,68.55) v1(117.35,67) v1(117.4,29.7) v1(117.4,28.4) v1(117.4,18.6) v1(117.5,78.6) v1(117.5,76.3) v1(117.5,72.3) v1(117.5,31.5) v1(117.5,26.3) v1(117.5,23.1) v1(117.6,74.3) v1(117.65,65.05) v1(117.7,48.85) v1(117.65,41.3) v1(117.7,33.2) v1(117.7,24.6) v1(117.7,15.8) v1(117.9,57.4) v1(117.9,21.3) v1(118,3.1) v1(118.1,70.1) v1(118.1,61.45) v1(118.1,59.5) v1(118.1,52.9) v1(118.1,39.2) v1(118.1,38.2) v1(118.1,35.5) v1(118.4,6.6) v1(118.65,51) v1(118.8,55.4) v1(118.9,48.15) v1(119,0.6) v1(119.3,8.5) v1(119.4,25.7) v1(119.6,67.85) v1(119.6,15.4) v1(119.7,66.2) v1(119.7,22.6) v1(119.7,20.3) v1(119.7,17.8) v1(120,8.6) v1(120.15,64) v1(120.3,72.4) v1(120.35,53.5) v1(120.3,9.3) v1(120.4,78.6) v1(120.4,76.5) v1(120.5,74.3) v1(120.45,57.1) v1(120.5,7.2) v1(120.7,70) v1(120.7,16.6) v1(120.8,14.1) v1(120.9,24.7) v1(121.1,51.7) v1(121.1,50.15) v1(121.55,66.2) v1(121.5,61.3) v1(121.5,7.9) v1(121.75,58.75) v1(122.2,44.4) v1(122.2,28.5) v1(122.2,12.5) v1(122.2,4.7) v1(122.4,26) v1(122.5,72.5) v1(122.45,57) v1(122.5,9.3) v1(122.5,1.8) v1(122.6,14.5) v1(122.6,10.7) v1(122.6,7.7) v1(122.8,78.6) v1(122.8,74.4) v1(122.9,76.5) v1(122.9,4.1) v1(123.1,49.8) v1(123.25,66.25) v1(123.2,61.9) v1(123.2,45.9) v1(123.2,29.8) v1(123.3,10.3) v1(123.4,25.5) v1(123.6,63.55) v1(123.7,14.6) v1(123.85,57) v1(123.8,23.3) v1(123.9,68.9) v1(123.9,54.9) v1(123.9,20.5) v1(123.95,67.9) v1(123.95,53) v1(124,50.9) v1(124,18.2) v1(124,16.2) v1(124,0.6) v1(124.3,78.6) v1(124.3,76.7) v1(124.3,74.6) v1(124.3,72.7) v1(124.3,60.6) v1(124.3,44.4) v1(124.3,28.4) v1(124.3,12.5) v1(124.4,70.5) v2(51.85,42.55) v2(52.85,47.55) v2(53.35,42.55) v2(59.9,87.65) v2(60.3,87.65) v2(60.3,87.3) v2(60.7,87.15) v2(61,86.9) v2(61.3,86.9) v2(61.3,86.45) v2(61.45,86.25)
